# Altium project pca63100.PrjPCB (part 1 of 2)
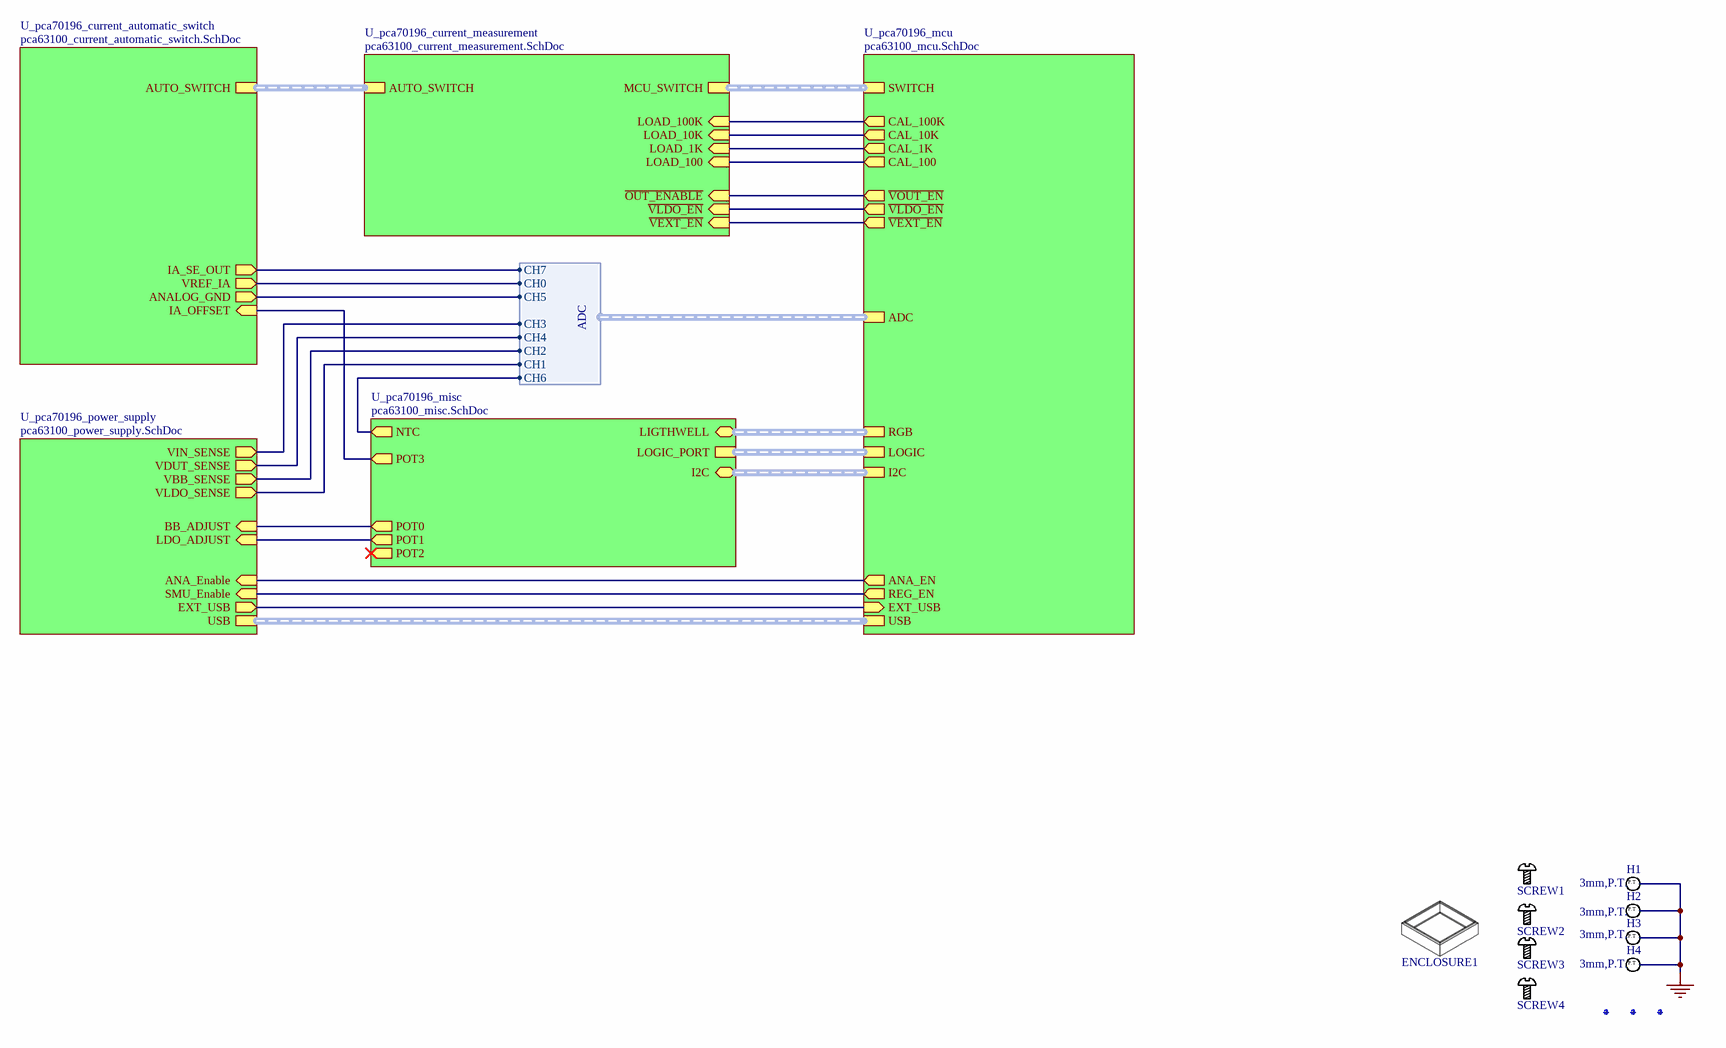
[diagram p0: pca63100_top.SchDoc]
Author: HANY; BoardThickness: 1.6mm; BoardTitle: Power Profiler Kit II; NrOfLayers: 4; Organization: Nordic Semiconductor; PCAName: pca63100; PCBNumber: 400491; PCBRevision: 0016HANY; PCBStackup: 4001; ProjectName: Power Profiler Kit II; ProjectNumber: PCA63100; Revision: 1.0.1; SilkscreenColor: White; SoldermaskColor: Blue; SurfaceFinish: ENIG
6 sheets, 280 parts. Net scope: hierarchical (ports join the sheet entries above them; power ports are global).
Board files: 400491.PcbDoc, 400491_panel.PcbDoc
Sheets:
  pca63100_top.SchDoc
    U_pca70196_current_automatic_switch = pca63100_current_automatic_switch.SchDoc
    U_pca70196_current_measurement = pca63100_current_measurement.SchDoc
    U_pca70196_power_supply = pca63100_power_supply.SchDoc
    U_pca70196_misc = pca63100_misc.SchDoc
    U_pca70196_mcu = pca63100_mcu.SchDoc

## Sheet pca63100_top.SchDoc: Power Profiler Kit II
size A3; Organization: Nordic Semiconductor; Revision: 1.0.1; SheetNumber: 1; SheetTotal: 6; Author: HANY; CompanyName: Nordic Semiconductor; DrawnBy: HANY; DocumentSize: A3

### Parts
ENCLOSURE1  Plastic Enclosure  [Enclosure_PPK2]  (value not drawn)
Fid1  Fiducial mark  [Fiducial_Round-Square]  (value not drawn)  (no BOM)
Fid2  Fiducial mark  [Fiducial_Round-Square]  (value not drawn)  (no BOM)
Fid3  Fiducial mark  [Fiducial_Round-Square]  (value not drawn)  (no BOM)
H1  3mm,P.T.  [HOLE_PT_3MM]  (no BOM)
H2  3mm,P.T.  [HOLE_PT_3MM]  (no BOM)
H3  3mm,P.T.  [HOLE_PT_3MM]  (no BOM)
H4  3mm,P.T.  [HOLE_PT_3MM]  (no BOM)
SCREW1  Screw  [Screw_25x50_pan_tx]  (value not drawn)
SCREW2  Screw  [Screw_25x50_pan_tx]  (value not drawn)
SCREW3  Screw  [Screw_25x50_pan_tx]  (value not drawn)
SCREW4  Screw  [Screw_25x50_pan_tx]  (value not drawn)

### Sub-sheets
U_pca70196_current_automatic_switch = pca63100_current_automatic_switch.SchDoc: IA_SE_OUT (out), IA_OFFSET (in), AUTO_SWITCH (harness SW), VREF_IA (out), ANALOG_GND (out)
U_pca70196_current_measurement = pca63100_current_measurement.SchDoc: ~{OUT_ENABLE} (in), LOAD_100 (in), LOAD_1K (in), LOAD_100K (in), LOAD_10K (in), ~{VEXT_EN} (in), MCU_SWITCH (harness SW), AUTO_SWITCH (harness SW), ~{VLDO_EN} (in)
U_pca70196_mcu = pca63100_mcu.SchDoc: RGB (harness LED), SWITCH (harness SW), I2C (harness I2C), ADC (harness ADC), CAL_10K (out), USB (harness USB), CAL_100K (out), CAL_1K (out), ~{VEXT_EN} (out), CAL_100 (out), ~{VLDO_EN} (out), ~{VOUT_EN} (out), EXT_USB (in), REG_EN (out), ANA_EN (out), LOGIC (harness LP)
U_pca70196_misc = pca63100_misc.SchDoc: POT0 (out), POT1 (out), POT2 (out), POT3 (out), LIGTHWELL (bidir, harness LED), I2C (bidir, harness I2C), NTC (out), LOGIC_PORT (harness LP)
U_pca70196_power_supply = pca63100_power_supply.SchDoc: USB (harness USB), BB_ADJUST (in), LDO_ADJUST (in), VDUT_SENSE (out), VIN_SENSE (out), VLDO_SENSE (out), VBB_SENSE (out), EXT_USB (out), ANA_Enable (in), SMU_Enable (in)

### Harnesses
ADC: CH0, CH1, CH2, CH3, CH4, CH5, CH6, CH7

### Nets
GND: H1.1 H2.1 H3.1 H4.1
P0.02/AIN0_VREF_IA: sheet U_pca70196_current_automatic_switch/VREF_IA, sheet U_pca70196_mcu/ADC.CH0
P0.03/AIN1_VLDO: sheet U_pca70196_power_supply/VLDO_SENSE, sheet U_pca70196_mcu/ADC.CH1
P0.04/AIN2_VBB: sheet U_pca70196_power_supply/VBB_SENSE, sheet U_pca70196_mcu/ADC.CH2
P0.05/AIN3_VIN: sheet U_pca70196_power_supply/VIN_SENSE, sheet U_pca70196_mcu/ADC.CH3
P0.06_VEXT_EN: sheet U_pca70196_current_measurement/~{VEXT_EN}, sheet U_pca70196_mcu/~{VEXT_EN}
P0.07_VLDO_EN: sheet U_pca70196_current_measurement/~{VLDO_EN}, sheet U_pca70196_mcu/~{VLDO_EN}
P0.08_ANA_EN: sheet U_pca70196_power_supply/ANA_Enable, sheet U_pca70196_mcu/ANA_EN
P0.20_CAL100K: sheet U_pca70196_current_measurement/LOAD_100K, sheet U_pca70196_mcu/CAL_100K
P0.21_CAL10K: sheet U_pca70196_current_measurement/LOAD_10K, sheet U_pca70196_mcu/CAL_10K
P0.22_CAL1K: sheet U_pca70196_current_measurement/LOAD_1K, sheet U_pca70196_mcu/CAL_1K
P0.23_CAL100: sheet U_pca70196_current_measurement/LOAD_100, sheet U_pca70196_mcu/CAL_100
P0.28/AIN4_VDUT: sheet U_pca70196_power_supply/VDUT_SENSE, sheet U_pca70196_mcu/ADC.CH4
P0.29/AIN5_AGND: sheet U_pca70196_current_automatic_switch/ANALOG_GND, sheet U_pca70196_mcu/ADC.CH5
P0.30/AIN6_NTC: sheet U_pca70196_misc/NTC, sheet U_pca70196_mcu/ADC.CH6
P0.31/AIN7_VSE_IA: sheet U_pca70196_current_automatic_switch/IA_SE_OUT, sheet U_pca70196_mcu/ADC.CH7
P1.04_VOUT_EN: sheet U_pca70196_current_measurement/~{OUT_ENABLE}, sheet U_pca70196_mcu/~{VOUT_EN}
P1.09_EXT_USB: sheet U_pca70196_power_supply/EXT_USB, sheet U_pca70196_mcu/EXT_USB
P1.13: sheet U_pca70196_power_supply/SMU_Enable, sheet U_pca70196_mcu/REG_EN
POT0: sheet U_pca70196_power_supply/BB_ADJUST, sheet U_pca70196_misc/POT0
POT1: sheet U_pca70196_power_supply/LDO_ADJUST, sheet U_pca70196_misc/POT1
POT3: sheet U_pca70196_current_automatic_switch/IA_OFFSET, sheet U_pca70196_misc/POT3

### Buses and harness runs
harness sheet U_pca70196_current_automatic_switch/AUTO_SWITCH = sheet U_pca70196_current_measurement/AUTO_SWITCH
harness sheet U_pca70196_current_measurement/MCU_SWITCH = sheet U_pca70196_mcu/SWITCH
harness sheet U_pca70196_mcu/I2C = sheet U_pca70196_misc/I2C
harness sheet U_pca70196_mcu/LOGIC = sheet U_pca70196_misc/LOGIC_PORT
harness sheet U_pca70196_mcu/RGB = sheet U_pca70196_misc/LIGTHWELL
harness sheet U_pca70196_mcu/USB = sheet U_pca70196_power_supply/USB

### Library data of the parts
ENCLOSURE1 = Enclosure_PPK2: PPK2 Moulded plastic casing; Manufacturer: Proto Labs, Inc.; Manufacturer Part Number: PPK plexi rev 1.2; Part number IPS: 4971; Pad Count: 0
Fid1-Fid3 = Fid-Mark-Round-Square: Artikkelnr Noca: N.A.; Pad Count: 1
H1-H4 = Hole_3MM_PT: Regular Plate Through, 3mm hole; Manufacturer: Nordic Semiconductor; Artikkelnr Noca: N.A.; Pad Count: 1
SCREW1-SCREW4 = Screw_25x50_pan_tx: Pan head, torx, 2.5x5mm screw; Manufacturer: Bossard; Manufacturer Part Number: 3205129; Part number IPS: 4972; Pad Count: 0

## Sheet pca63100_current_automatic_switch.SchDoc: Power Profiler Kit II
size A3; Organization: Nordic Semiconductor; Revision: 1.0.1; SheetNumber: 5; SheetTotal: 6; Author: HANY; CompanyName: Nordic Semiconductor; DrawnBy: HANY; DocumentSize: A3
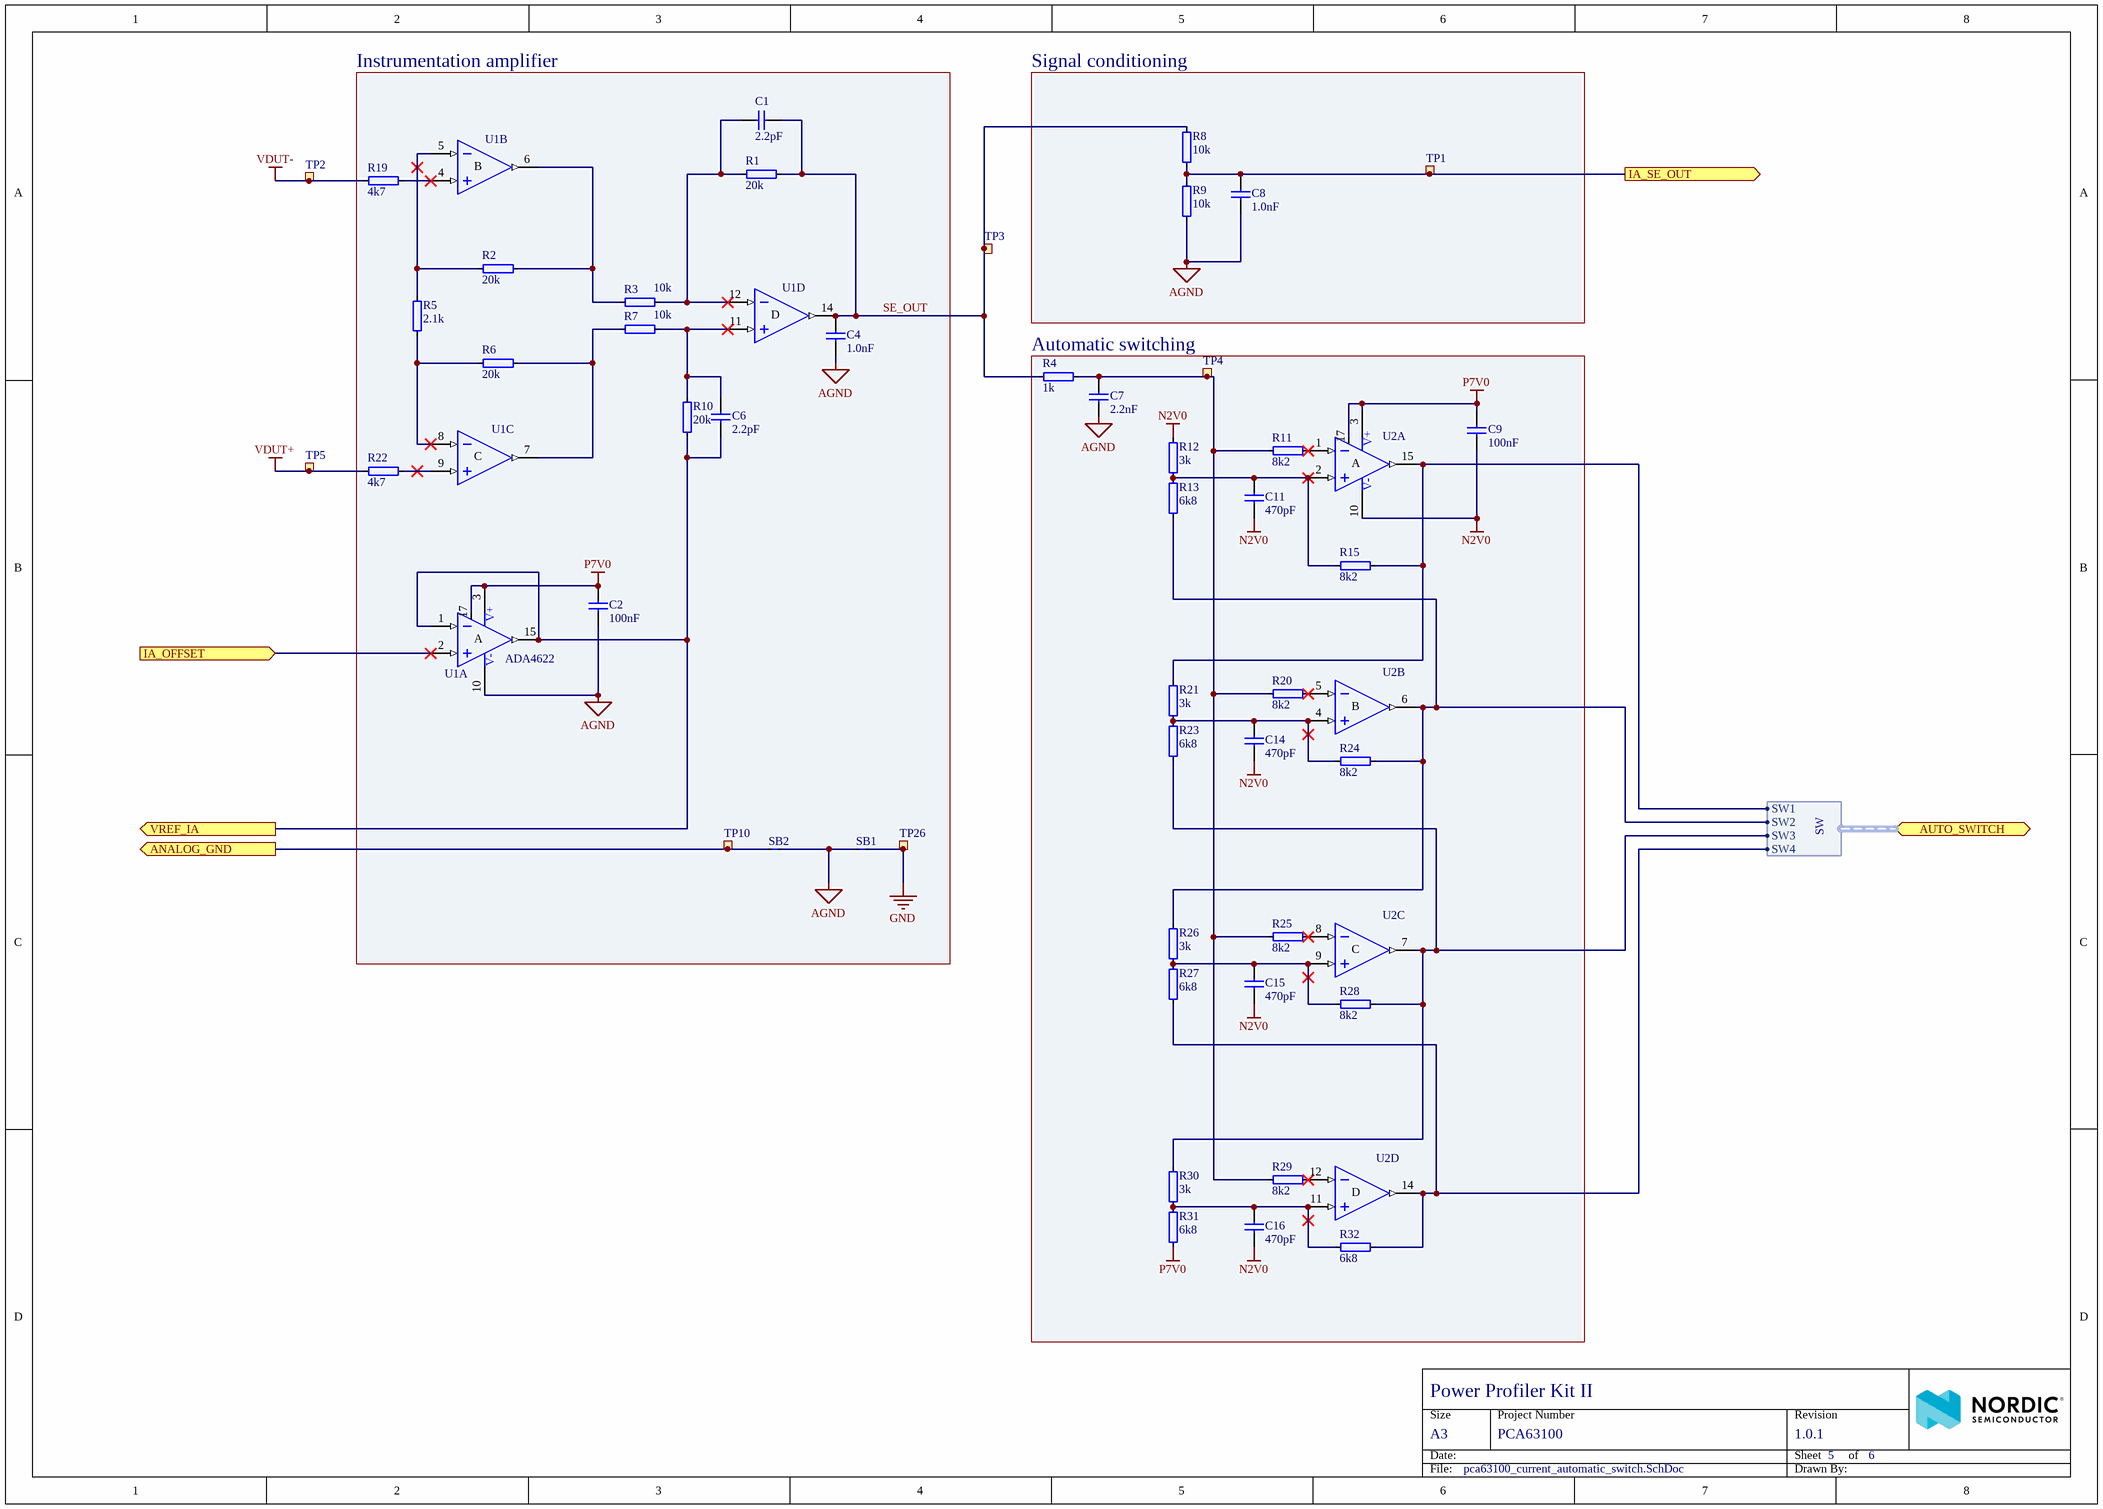
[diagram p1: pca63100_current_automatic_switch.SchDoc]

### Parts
C1  2.2pF  [CAPC0603X03L_C]
C2  100nF  [CAPC0603X03L_C]
C4  1.0nF  [CAPC0603X03L_C]
C6  2.2pF  [CAPC0603X03L_C]
C7  2.2nF  [CAPC0603X03L_C]
C8  1.0nF  [CAPC0603X03L_C]
C9  100nF  [CAPC0603X03L_C]
C11  470pF  [CAPC0603X03L_C]
C14  470pF  [CAPC0603X03L_C]
C15  470pF  [CAPC0603X03L_C]
C16  470pF  [CAPC0603X03L_C]
R1  20k  [RESC0603X03L_C]
R2  20k  [RESC0603X03L_C]
R3  10k  [RESC0603X03L_C]
R4  1k  [RESC0603X03L_C]
R5  2.1k  [RESC0603X03L_C]
R6  20k  [RESC0603X03L_C]
R7  10k  [RESC0603X03L_C]
R8  10k  [RESC0603X03L_C]
R9  10k  [RESC0603X03L_C]
R10  20k  [RESC0603X03L_C]
R11  8k2  [RESC0603X03L_C]
R12  3k  [RESC0603X03L_C]
R13  6k8  [RESC0603X03L_C]
R15  8k2  [RESC0603X03L_C]
R19  4k7  [RESC0603X03L_C]
R20  8k2  [RESC0603X03L_C]
R21  3k  [RESC0603X03L_C]
R22  4k7  [RESC0603X03L_C]
R23  6k8  [RESC0603X03L_C]
R24  8k2  [RESC0603X03L_C]
R25  8k2  [RESC0603X03L_C]
R26  3k  [RESC0603X03L_C]
R27  6k8  [RESC0603X03L_C]
R28  8k2  [RESC0603X03L_C]
R29  8k2  [RESC0603X03L_C]
R30  3k  [RESC0603X03L_C]
R31  6k8  [RESC0603X03L_C]
R32  6k8  [RESC0603X03L_C]
SB1  NetTie_200um  [NetTie_200um]  (value not drawn)  (net tie, no BOM)
SB2  NetTie_200um  [NetTie_200um]  (value not drawn)  (net tie, no BOM)
TP1  Ø0.7mm,SMD  [TP_SMD_Ø0.7mm]  (value not drawn)  (no BOM)
TP2  Ø0.7mm,SMD  [TP_SMD_Ø0.7mm]  (value not drawn)  (no BOM)
TP3  Ø0.7mm,SMD  [TP_SMD_Ø0.7mm]  (value not drawn)  (no BOM)
TP4  Ø0.7mm,SMD  [TP_SMD_Ø0.7mm]  (value not drawn)  (no BOM)
TP5  Ø0.7mm,SMD  [TP_SMD_Ø0.7mm]  (value not drawn)  (no BOM)
TP10  Ø0.7mm,SMD  [TP_SMD_Ø0.7mm]  (value not drawn)  (no BOM)
TP26  Ø0.7mm,SMD  [TP_SMD_Ø0.7mm]  (value not drawn)  (no BOM)
U1  ADA4622  [QFN65P400X400X80_HS-17N]  (parts A,B,C,D of 4)
U2  ADA4622  [QFN65P400X400X80_HS-17N]  (value not drawn)  (parts A,B,C,D of 4)

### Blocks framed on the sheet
Instrumentation amplifier: C1 C2 C4 C6 R1-R3 R5-R7 R10 R19 R22 SB1 SB2 TP10 TP26 U1
Signal conditioning: C8 R8 R9 TP1
Automatic switching: C7 C9 C11 C14-C16 R4 R11-R13 R15 R20 R21 R23-R32 TP4 U2

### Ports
ANALOG_GND (out), AUTO_SWITCH (bidir, harness SW), IA_OFFSET (in), IA_SE_OUT (out), VREF_IA (out)

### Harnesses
SW: SW1, SW2, SW3, SW4

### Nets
AGND: C2.2 C4.1 C7.1 C8.1 R9.1 SB1.1 SB2.2 U1.10(VSS)
GND: SB1.2 TP26.1
N2V0: C9.1 C11.1 C14.1 C15.1 C16.1 R12.2 U2.10(VSS)
P7V0: C2.1 C9.2 R31.1 U1.3(VDD) U1.17(EPAD) U2.3(VDD) U2.17(EPAD)
VDUT+: R22.2 TP5.1
VDUT-: R19.2 TP2.1
AUTO_SW1: R15.2 R21.2 U2.15(OUTA) ; port AUTO_SWITCH.SW1
AUTO_SW2: R13.1 R24.2 R26.2 U2.6(OUTB) ; port AUTO_SWITCH.SW2
AUTO_SW3: R23.1 R28.2 R30.2 U2.7(OUTC) ; port AUTO_SWITCH.SW3
AUTO_SW4: R27.1 R32.2 U2.14(OUTD) ; port AUTO_SWITCH.SW4
P0.02/AIN0_VREF_IA: C6.1 R10.1 U1.1(IN_A-) U1.15(OUTA) ; port VREF_IA
P0.29/AIN5_AGND: SB2.1 TP10.1 ; port ANALOG_GND
P0.31/AIN7_VSE_IA: C8.2 R8.2 R9.2 TP1.1 ; port IA_SE_OUT
POT3: U1.2(IN_A+) ; port IA_OFFSET
SE_OUT: C1.2 C4.2 R1.2 R4.1 R8.1 TP3.1 U1.14(OUTD)
NetC1_1: C1.1 R1.1 R3.2 U1.12(IN_D-)
NetC6_2: C6.2 R7.2 R10.2 U1.11(IN_D+)
NetC7_2: C7.2 R4.2 R11.1 R20.1 R25.1 R29.1 TP4.1
NetC11_2: C11.2 R12.1 R13.2 R15.1 U2.2(IN_A+)
NetC14_2: C14.2 R21.1 R23.2 R24.1 U2.4(IN_B+)
NetC15_2: C15.2 R26.1 R27.2 R28.1 U2.9(IN_C+)
NetC16_2: C16.2 R30.1 R31.2 R32.1 U2.11(IN_D+)
NetR2_1: R2.1 R5.2 U1.5(IN_B-)
NetR2_2: R2.2 R3.1 U1.6(OUTB)
NetR5_1: R5.1 R6.1 U1.8(IN_C-)
NetR6_2: R6.2 R7.1 U1.7(OUTC)
NetR11_2: R11.2 U2.1(IN_A-)
NetR19_1: R19.1 U1.4(IN_B+)
NetR20_2: R20.2 U2.5(IN_B-)
NetR22_1: R22.1 U1.9(IN_C+)
NetR25_2: R25.2 U2.8(IN_C-)
NetR29_2: R29.2 U2.12(IN_D-)

Not connected (* = marked no-connect by the designer): U1 13(NIC) 16(NIC); U2 13(NIC) 16(NIC)

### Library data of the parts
C1 C6 = C0201-2.2p: Chip Cap 0201; Note: Chip Cap 1%; Artikkelnr Noca: N.A.; Pad Count: 2
C2 C9 = C0201-100n: Capacitor, X5R, ±10%; Part number IPS: 00000001248, 00000002505; Note: 16V; Artikkelnr Noca: N.A.; Pad Count: 2
C4 C8 = C0201-1n0: Capacitor, X7R, ±10%; Part number IPS: 00000003206; Note: 16V; Artikkelnr Noca: N.A.; Pad Count: 2
C7 = C0201-2n2: Capacitor, X7R, ±10%, 10V; Part number IPS: 00000001778; Artikkelnr Noca: N.A.; Pad Count: 2
C11 C14-C16 = C0201-470p: Chip Cap 0201; Part number IPS: 00000005775; Note: Chip Cap 1%; Artikkelnr Noca: N.A.; Pad Count: 2
R1 R2 R6 R10 = R0201-20k_0.1%: Resistor, ±0.1%, 0.031W; Part number IPS: 00000004785; Note: Chip Res 0.1%; Artikkelnr Noca: N.A.; Pad Count: 2
R3 R7-R9 = R0201-10k_0.1%: Resistor, ±0.1%, 0.031W; Part number IPS: 00000004786; Note: Chip Res 0.1%; Artikkelnr Noca: N.A.; Pad Count: 2
R4 = R0201-1k0: Resistor, ±1%, 0.05W; Part number IPS: 00000005786; Note: Chip Res 1%; Artikkelnr Noca: N.A.; Pad Count: 2
R5 = R0201-2k1: RES SMD 2.1K OHM 1% 1/20W 0201; Manufacturer: Panasonic; Manufacturer Part Number: ERJ-1GEF2101C; Part number IPS: 00000004787; Note: Chip Res 1%; Artikkelnr Noca: N.A.; Pad Count: 2
R11 R15 R20 R24 R25 R28 R29 = R0201-8k2: Resistor, ±1%, 0.05W; Part number IPS: 00000004788; Note: Chip Res 1%; Artikkelnr Noca: N.A.; Pad Count: 2
R12 R21 R26 R30 = R0201-3k0: Resistor, ±1%, 0.05W; Part number IPS: 00000001688; Note: Chip Res 1%; Artikkelnr Noca: N.A.; Pad Count: 2
R13 R23 R27 R31 R32 = R0201-6k8: Resistor, ±1%, 0.05W; Part number IPS: 00000001705; Note: Chip Res 1%; Artikkelnr Noca: N.A.; Pad Count: 2
R19 R22 = R0201-4k7: Resistor, ±1%, 0.05W; Part number IPS: 00000001706; Note: Chip Res 1%; Artikkelnr Noca: N.A.; Pad Count: 2
SB1 SB2 = NetTie 0.2mm: Net Tie; Artikkelnr Noca: N.A.; Pad Count: 2
TP1-TP5 TP10 TP26 = TP_SMD_Ø0.7MM: 0.7mm circular SMD testpad; Manufacturer: Nordic Semiconductor; Artikkelnr Noca: N.A.; Pad Count: 1
U1 U2 = ADA4622-4: J-FET Amplifier 4 Circuit Rail-to-Rail 16-LFCSP (4x4); Manufacturer: Analog Devices; Manufacturer Part Number: ADA4622-4ACPZ-RL; Part number IPS: 00000004963; Artikkelnr Noca: N.A.; Pad Count: 17

## Sheet pca63100_current_measurement.SchDoc: Power Profiler Kit II
size A3; Organization: Nordic Semiconductor; Revision: 1.0.1; SheetNumber: 4; SheetTotal: 6; Author: HANY; CompanyName: Nordic Semiconductor; DrawnBy: HANY; DocumentSize: A3
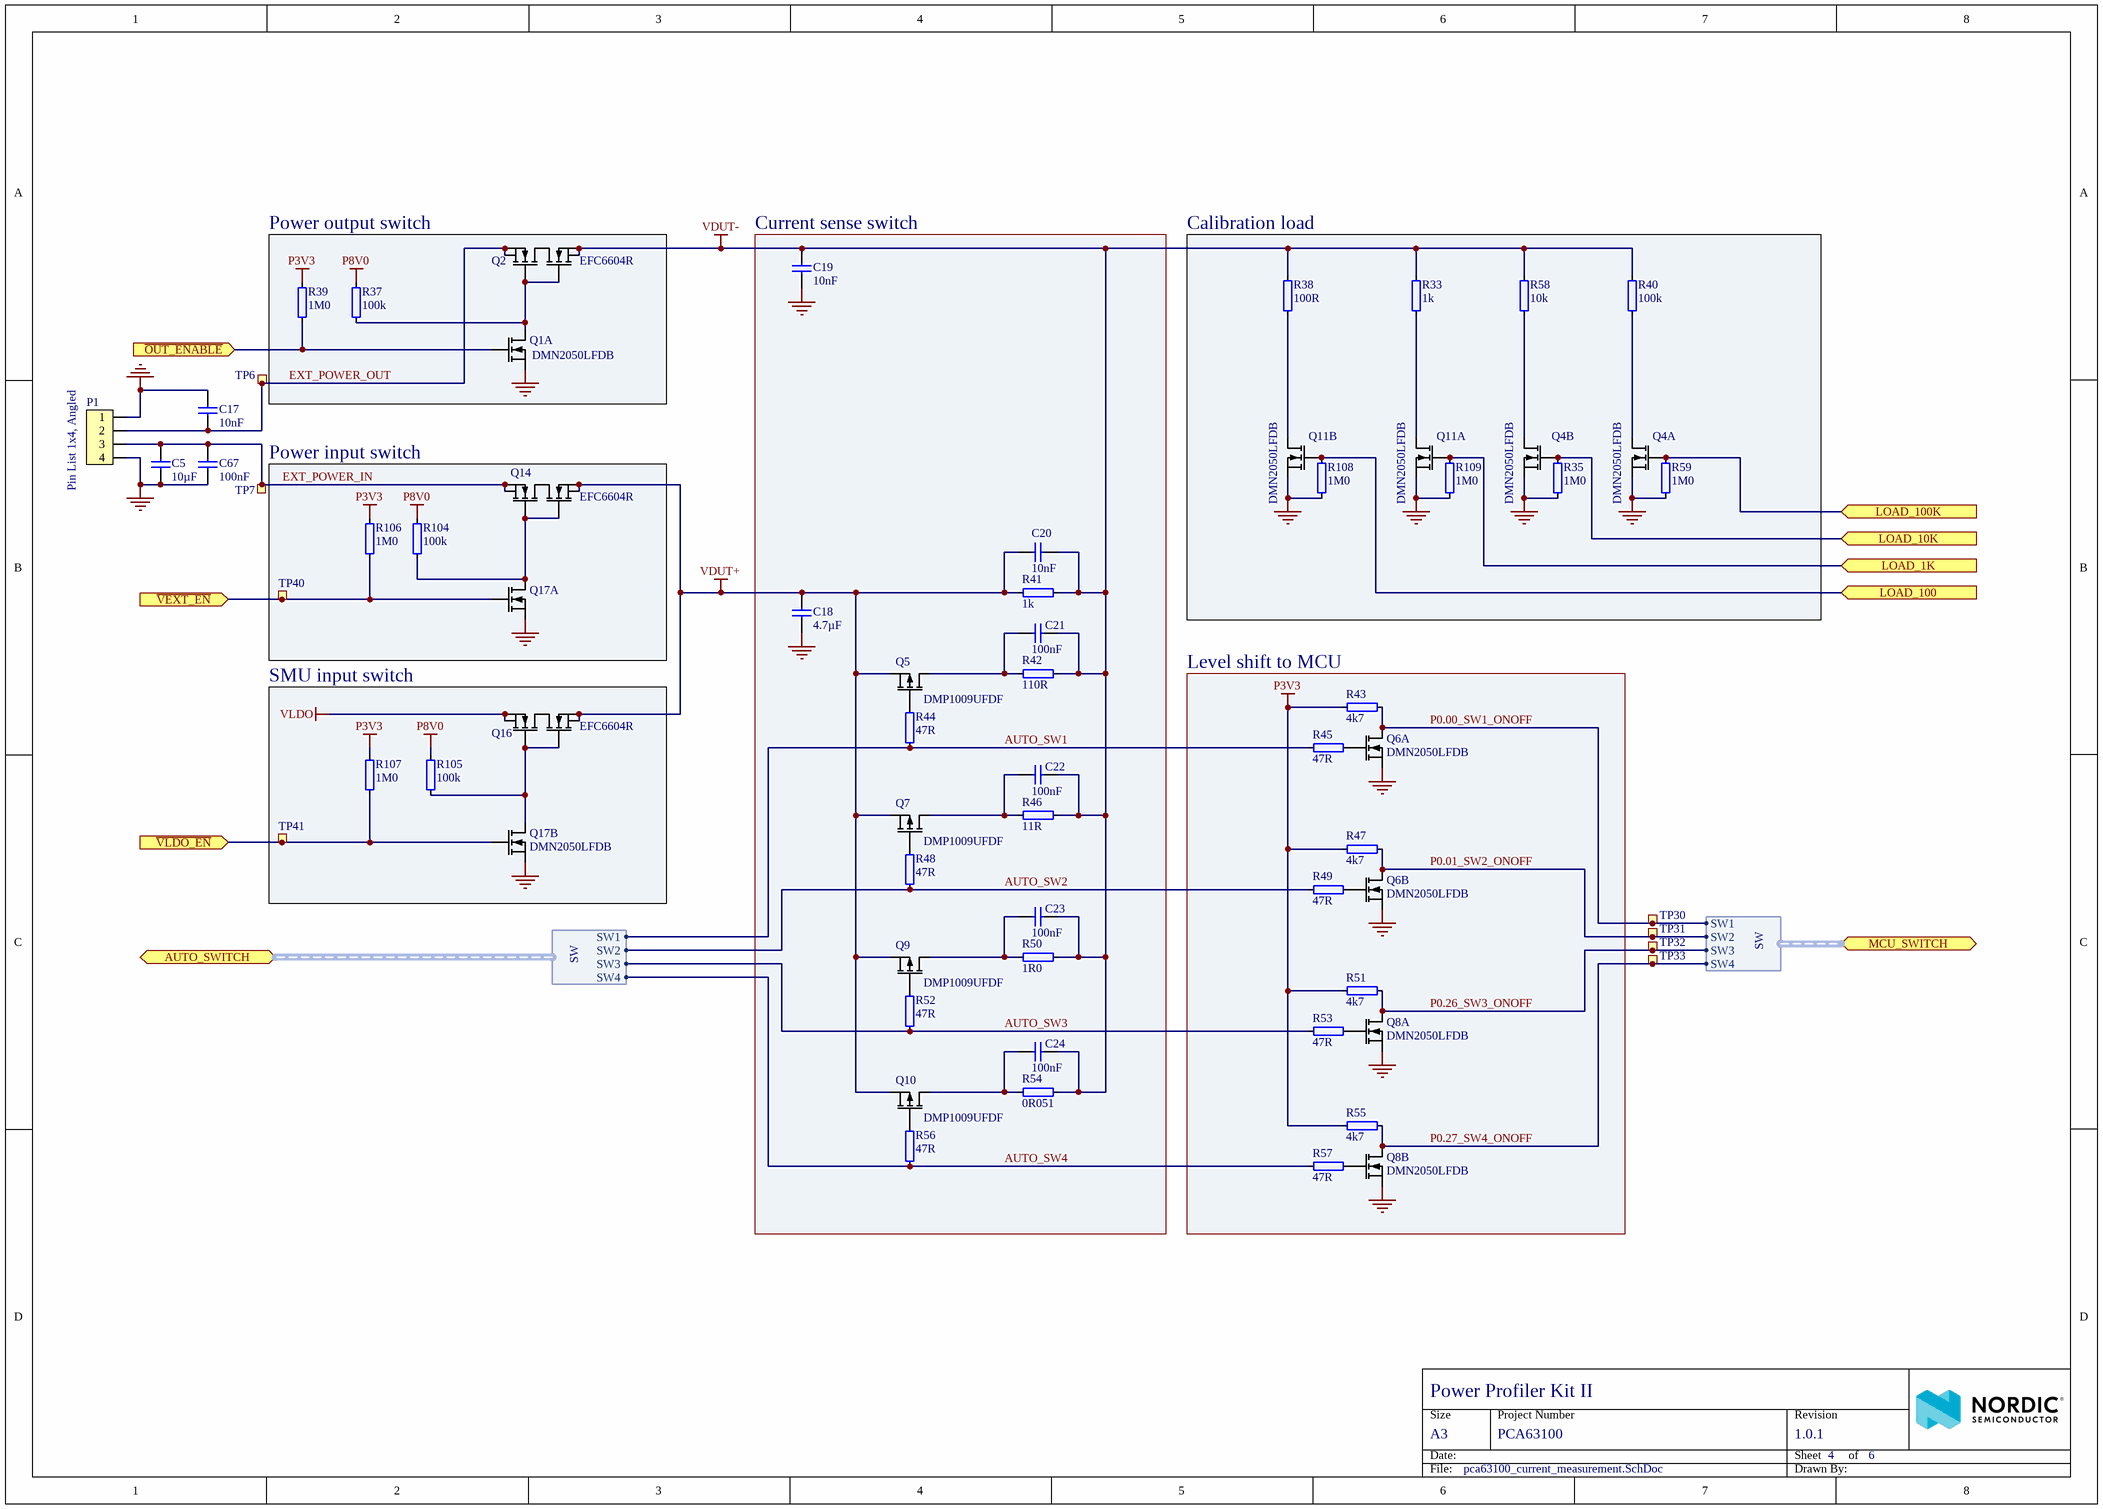
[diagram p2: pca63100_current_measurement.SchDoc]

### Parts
C5  10µF  [CAPC1608X06L]
C17  10nF  [CAPC0603X03L_C]
C18  4.7µF  [CAPC1005X04L]
C19  10nF  [CAPC0603X03L_C]
C20  10nF  [CAPC0603X03L_C]
C21  100nF  [CAPC0603X03L_C]
C22  100nF  [CAPC0603X03L_C]
C23  100nF  [CAPC0603X03L_C]
C24  100nF  [CAPC0603X03L_C]
C67  100nF  [CAPC0603X03L_C]
P1  Pin List 1x4, Angled  [LIST_ANG_1x4-SMD-2.54MM]
Q1  DMN2050LFDB  [DFN65P200X60_HS-6N]  (part A of 2)
Q2  EFC6604R  [BGA6C65P2X3_146X191X22]
Q4  DMN2050LFDB  [DFN65P200X60_HS-6N]  (parts A,B of 2)
Q5  DMP1009UFDF  [UDFN65P200X200X60_HS-6N]
Q6  DMN2050LFDB  [DFN65P200X60_HS-6N]  (parts A,B of 2)
Q7  DMP1009UFDF  [UDFN65P200X200X60_HS-6N]
Q8  DMN2050LFDB  [DFN65P200X60_HS-6N]  (parts A,B of 2)
Q9  DMP1009UFDF  [UDFN65P200X200X60_HS-6N]
Q10  DMP1009UFDF  [UDFN65P200X200X60_HS-6N]
Q11  DMN2050LFDB  [DFN65P200X60_HS-6N]  (parts A,B of 2)
Q14  EFC6604R  [BGA6C65P2X3_146X191X22]
Q16  EFC6604R  [BGA6C65P2X3_146X191X22]
Q17  DMN2050LFDB  [DFN65P200X60_HS-6N]  (value not drawn)  (parts A,B of 2)
R33  1k  [RESC1005X04L]
R35  1M0  [RESC0603X03L_C]
R37  100k  [RESC0603X03L_C]
R38  100R  [RESC2012X11L]
R39  1M0  [RESC0603X03L_C]
R40  100k  [RESC1005X04L]
R41  1k  [RESC1005X04L]
R42  110R  [RESC1005X04L]
R43  4k7  [RESC0603X03L_C]
R44  47R  [RESC0603X03L_C]
R45  47R  [RESC0603X03L_C]
R46  11R  [RESC1005X04L]
R47  4k7  [RESC0603X03L_C]
R48  47R  [RESC0603X03L_C]
R49  47R  [RESC0603X03L_C]
R50  1R0  [RESC1005X04L]
R51  4k7  [RESC0603X03L_C]
R52  47R  [RESC0603X03L_C]
R53  47R  [RESC0603X03L_C]
R54  0R051  [RESC1005X04L]
R55  4k7  [RESC0603X03L_C]
R56  47R  [RESC0603X03L_C]
R57  47R  [RESC0603X03L_C]
R58  10k  [RESC0603X03L_C]
R59  1M0  [RESC0603X03L_C]
R104  100k  [RESC0603X03L_C]
R105  100k  [RESC0603X03L_C]
R106  1M0  [RESC0603X03L_C]
R107  1M0  [RESC0603X03L_C]
R108  1M0  [RESC0603X03L_C]
R109  1M0  [RESC0603X03L_C]
TP6  Ø1.5mm,SMD  [TP_SMD_Ø1.5mm]  (value not drawn)  (no BOM)
TP7  Ø1.5mm,SMD  [TP_SMD_Ø1.5mm]  (value not drawn)  (no BOM)
TP30  Ø0.7mm,SMD  [TP_SMD_Ø0.7mm]  (value not drawn)  (no BOM)
TP31  Ø0.7mm,SMD  [TP_SMD_Ø0.7mm]  (value not drawn)  (no BOM)
TP32  Ø0.7mm,SMD  [TP_SMD_Ø0.7mm]  (value not drawn)  (no BOM)
TP33  Ø0.7mm,SMD  [TP_SMD_Ø0.7mm]  (value not drawn)  (no BOM)
TP40  Ø0.7mm,SMD  [TP_SMD_Ø0.7mm]  (value not drawn)  (no BOM)
TP41  Ø0.7mm,SMD  [TP_SMD_Ø0.7mm]  (value not drawn)  (no BOM)

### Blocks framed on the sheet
Power output switch: Q1 Q2 R37 R39
Current sense switch: C18-C24 Q5 Q7 Q9 Q10 R41 R42 R44 R46 R48 R50 R52 R54 R56
Calibration load: Q4 Q11 R33 R35 R38 R40 R58 R59 R108 R109
Power input switch: Q14 Q17 R104 R106 TP40
SMU input switch: Q16 Q17 R105 R107 TP41
Level shift to MCU: Q6 Q8 R43 R45 R47 R49 R51 R53 R55 R57

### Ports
AUTO_SWITCH (bidir, harness SW), LOAD_1K (in), LOAD_10K (in), LOAD_100 (in), LOAD_100K (in), MCU_SWITCH (bidir, harness SW), ~{OUT_ENABLE} (in), ~{VEXT_EN} (in), ~{VLDO_EN} (in)

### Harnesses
SW: SW1, SW2, SW3, SW4

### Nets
GND: C5.2 C17.1 C18.2 C19.1 C67.2 P1.1 P1.4 Q1.1(S1) Q4.1(S1) Q4.4(S2) Q6.1(S1) Q6.4(S2) Q8.1(S1) Q8.4(S2) Q11.1(S1) Q11.4(S2) Q17.1(S1) Q17.4(S2) R35.1 R59.1 R108.1 R109.1
P3V3: R39.2 R43.2 R47.2 R51.2 R55.2 R106.2 R107.2
P8V0: R37.1 R104.2 R105.2
VDUT+: C18.1 C20.1 Q5.2(S) Q7.2(S) Q9.2(S) Q10.2(S) Q14.1(S1) Q14.3(S2) Q16.1(S1) Q16.3(S2) R41.1
VDUT-: C19.2 C20.2 C21.2 C22.2 C23.2 C24.2 Q2.1(S1) Q2.3(S2) R33.1 R38.2 R40.2 R41.2 R42.2 R46.2 R50.2 R54.1 R58.1
VLDO: Q16.4(S2) Q16.6(S2)
AUTO_SW1: R44.1 R45.2 ; port AUTO_SWITCH.SW1
AUTO_SW2: R48.1 R49.2 ; port AUTO_SWITCH.SW2
AUTO_SW3: R52.1 R53.2 ; port AUTO_SWITCH.SW3
AUTO_SW4: R56.1 R57.2 ; port AUTO_SWITCH.SW4
EXT_POWER_IN: C5.1 C67.1 P1.3 Q14.4(S2) Q14.6(S2) TP7.1
EXT_POWER_OUT: C17.2 P1.2 Q2.4(S2) Q2.6(S2) TP6.1
P0.00_SW1_ONOFF: Q6.6(D1) R43.1 TP30.1 ; port MCU_SWITCH.SW1
P0.01_SW2_ONOFF: Q6.3(D2) R47.1 TP31.1 ; port MCU_SWITCH.SW2
P0.06_VEXT_EN: Q17.2(G1) R106.1 TP40.1 ; port ~{VEXT_EN}
P0.07_VLDO_EN: Q17.5(G2) R107.1 TP41.1 ; port ~{VLDO_EN}
P0.20_CAL100K: Q4.2(G1) R59.2 ; port LOAD_100K
P0.21_CAL10K: Q4.5(G2) R35.2 ; port LOAD_10K
P0.22_CAL1K: Q11.2(G1) R109.2 ; port LOAD_1K
P0.23_CAL100: Q11.5(G2) R108.2 ; port LOAD_100
P0.26_SW3_ONOFF: Q8.6(D1) R51.1 TP32.1 ; port MCU_SWITCH.SW3
P0.27_SW4_ONOFF: Q8.3(D2) R55.1 TP33.1 ; port MCU_SWITCH.SW4
P1.04_VOUT_EN: Q1.2(G1) R39.1 ; port ~{OUT_ENABLE}
NetC21_1: C21.1 Q5.3(D) R42.1
NetC22_1: C22.1 Q7.3(D) R46.1
NetC23_1: C23.1 Q9.3(D) R50.1
NetC24_1: C24.1 Q10.3(D) R54.2
NetQ1_6: Q1.6(D1) Q2.2(G1) Q2.5(G2) R37.2
NetQ4_3: Q4.3(D2) R58.2
NetQ4_6: Q4.6(D1) R40.1
NetQ5_1: Q5.1(G) R44.2
NetQ6_2: Q6.2(G1) R45.1
NetQ6_5: Q6.5(G2) R49.1
NetQ7_1: Q7.1(G) R48.2
NetQ8_2: Q8.2(G1) R53.1
NetQ8_5: Q8.5(G2) R57.1
NetQ9_1: Q9.1(G) R52.2
NetQ10_1: Q10.1(G) R56.2
NetQ11_3: Q11.3(D2) R38.1
NetQ11_6: Q11.6(D1) R33.2
NetQ14_2: Q14.2(G1) Q14.5(G2) Q17.6(D1) R104.1
NetQ16_2: Q16.2(G1) Q16.5(G2) Q17.3(D2) R105.1

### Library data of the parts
C5 = 0603-10u-10V-X7T-GRM188: CAP CER 10UF 10V X7T 0603; Manufacturer: Murata; Manufacturer Part Number: GRM188D71A106MA73; Part number IPS: 00000004696; Note: 10VDC; Artikkelnr Noca: N.A; Pad Count: 2
C17 C19 C20 = C0201-10n: Capacitor, X7R, ±10%; Part number IPS: 00000003480; Note: 10V; Artikkelnr Noca: N.A.; Pad Count: 2
C18 = C0402-4µ7: Capacitor, X5R, ±20%; Part number IPS: 00000001251, 00000007165; Note: 10V; Artikkelnr Noca: 20039482; Pad Count: 2
C21-C24 C67 = C0201-100n: as C2 on sheet pca63100_current_automatic_switch
P1 = Pin List Ang 1x4 SMD, 2.54mm: Pin List 1x4, 2.54mm (100mil), Right Angled, SMD; Part number IPS: 00000004780; Artikkelnr Noca: N.A.; Pad Count: 4
Q1 Q4 Q6 Q8 Q11 Q17 = DMN2050LFDB: Dual N Ch MOFET, 3.3A, 45mOhm @ 5A, 4.5V, 730mW; Manufacturer: Diodes Incorporated; Manufacturer Part Number: DMN2050LFDB-7; Part number IPS: 00000004782; Artikkelnr Noca: N.A.; Pad Count: 6
Q2 Q14 Q16 = EFC6604R: Dual MOSFET, Dual N Channel, 13 A, 12 V, 0.009 ohm, 4.5 V, 2.5 V; Manufacturer: ON Semiconductor; Manufacturer Part Number: EFC6604R-TR; Part number IPS: 00000004783; Artikkelnr Noca: N.A.; Pad Count: 6
Q5 Q7 Q9 Q10 = DMP1009UFDF: P Ch MOFET, 11A, 30mOhm max, 2W; Manufacturer: Diodes Incorporated; Part number IPS: 00000004784; Artikkelnr Noca: N.A.; Pad Count: 6
R33 R41 = R0402-1k0_0.1%: Resistor, ±0.1%, 0.063W; Part number IPS: 00000004790; Note: Chip Res 0.1%; Artikkelnr Noca: 27469397; Pad Count: 2
R35 R39 R59 R106-R109 = R0201-1M0: Resistor, ±1%, 0.05W; Part number IPS: 00000001418; Note: Chip Res 1%; Artikkelnr Noca: N.A.; Pad Count: 2
R37 R104 R105 = R0201-100k: Resistor, ±1%, 0.05W; Part number IPS: 00000001419; Note: Chip Res 1%; Artikkelnr Noca: N.A.; Pad Count: 2
R38 = R0805-100: Resistor, ±1%, 0.125W; Part number IPS: 00000004791; Note: Chip Res 1%; Artikkelnr Noca: 27089049; Pad Count: 2
R40 = R0402-100k_0.1%: Resistor, ±0.1%, 0.063W; Part number IPS: 00000004792; Note: Chip Res 1%; Artikkelnr Noca: N.A.; Pad Count: 2
R42 = R0402-110: Resistor, ±1%, 0.063W; Part number IPS: 00000004793; Note: Chip Res 1%; Artikkelnr Noca: N.A.; Pad Count: 2
R43 R47 R51 R55 = R0201-4k7: as R19 on sheet pca63100_current_automatic_switch
R44 R45 R48 R49 R52 R53 R56 R57 = R0201-47R: Resistor, ±1%, 0.05W; Part number IPS: 00000004794; Note: Chip Res 1%; Artikkelnr Noca: N.A.; Pad Count: 2
R46 = R0402-11R: Resistor, ±1%, 0.063W; Part number IPS: 00000007807; Note: Chip Res 1%; Artikkelnr Noca: N.A.; Pad Count: 2
R50 = R0402-1R0: Resistor, ±1%, 0.063W; Part number IPS: 00000004795; Note: Chip Res 1%; Artikkelnr Noca: 27049001; Pad Count: 2
R54 = R0402-0R051: RES SMD 0.051 OHM 1% 1/4W 0402; Manufacturer: Panasonic; Manufacturer Part Number: ERJ-2BWFR051X; Part number IPS: 00000004796; Note: Chip Res 1%; Artikkelnr Noca: N.A.; Pad Count: 2
R58 = R0201-10k_0.1%: as R3 on sheet pca63100_current_automatic_switch
TP6 TP7 = TP_SMD_Ø1.5MM: 1.5mm circular SMD testpad; Manufacturer: Nordic Semiconductor; Artikkelnr Noca: N.A.; Pad Count: 1
TP30-TP33 TP40 TP41 = TP_SMD_Ø0.7MM: as TP1 on sheet pca63100_current_automatic_switch

## Sheet pca63100_power_supply.SchDoc: Power Profiler Kit II
size A3; Organization: Nordic Semiconductor; Revision: 1.0.1; SheetNumber: 3; SheetTotal: 6; Author: HANY; CompanyName: Nordic Semiconductor; DrawnBy: HANY; DocumentSize: A3
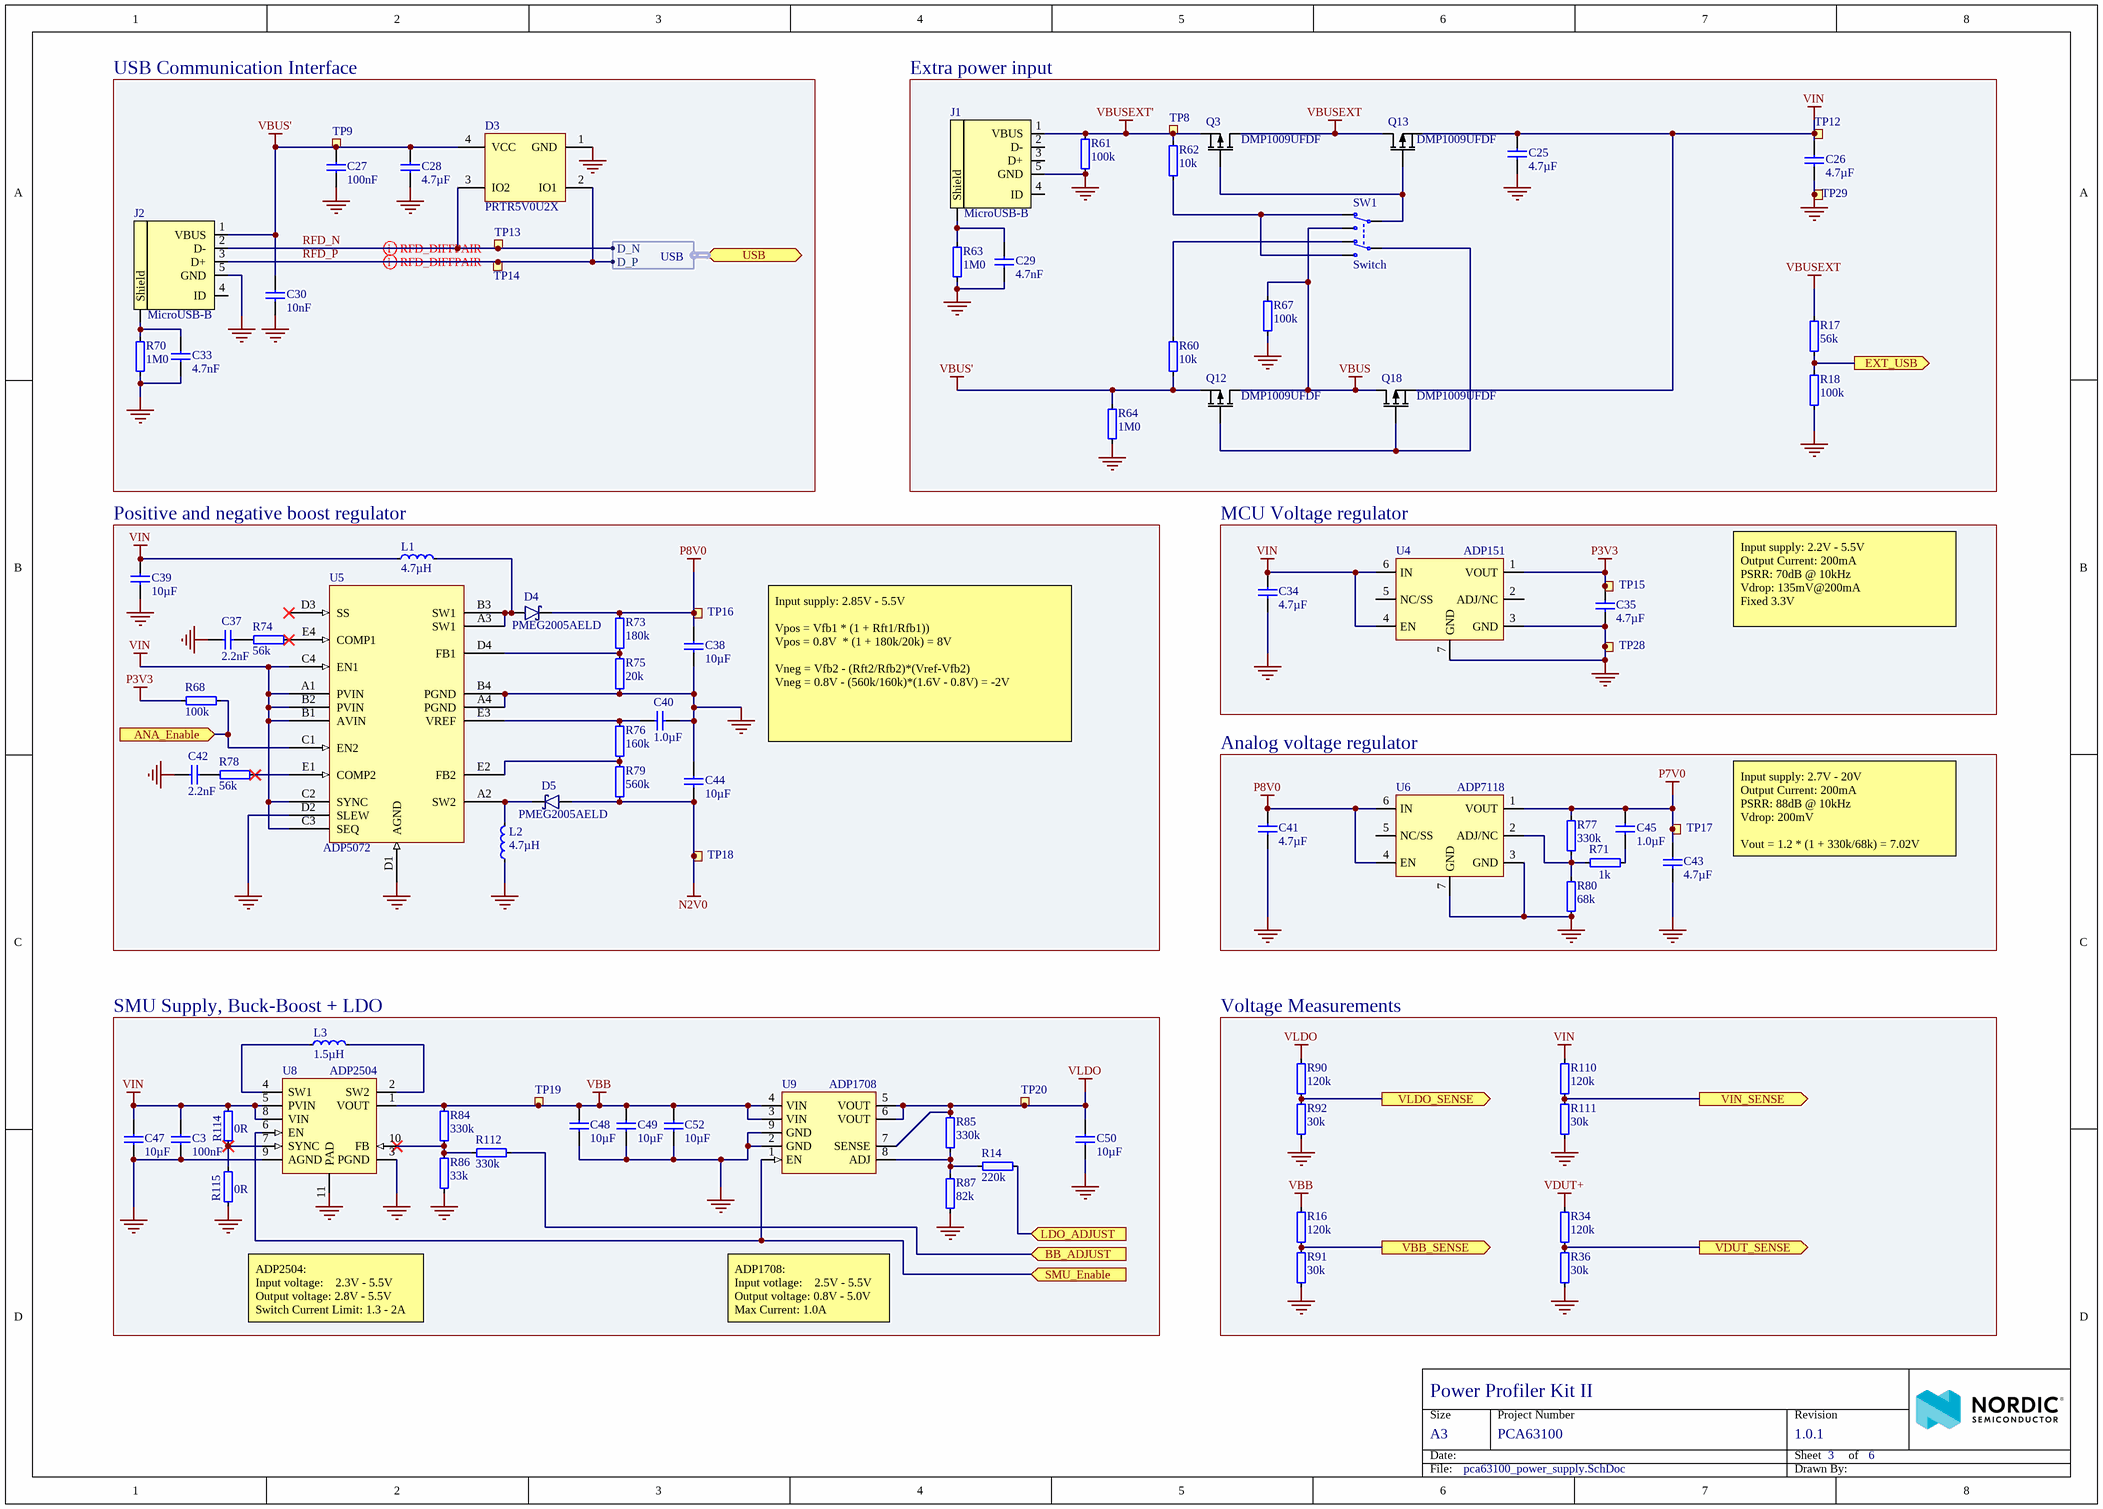
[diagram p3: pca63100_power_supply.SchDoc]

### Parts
C3  100nF  [CAPC0603X03L_C]
C25  4.7µF  [CAPC1005X04L]
C26  4.7µF  [CAPC1005X04L]
C27  100nF  [CAPC0603X03L_C]
C28  4.7µF  [CAPC1005X04L]
C29  4.7nF  [CAPC0603X03L_C]
C30  10nF  [CAPC0603X03L_C]
C33  4.7nF  [CAPC0603X03L_C]
C34  4.7µF  [CAPC1005X04L]
C35  4.7µF  [CAPC1005X04L]
C37  2.2nF  [CAPC0603X03L_C]
C38  10µF  [CAPC1608X06L]
C39  10µF  [CAPC1608X06L]
C40  1.0µF  [CAPC1005X04L]
C41  4.7µF  [CAPC1005X04L]
C42  2.2nF  [CAPC0603X03L_C]
C43  4.7µF  [CAPC1005X04L]
C44  10µF  [CAPC1608X06L]
C45  1.0µF  [CAPC0603X03L_C]
C47  10µF  [CAPC1608X06L]
C48  10µF  [CAPC1608X06L]
C49  10µF  [CAPC1608X06L]
C50  10µF  [CAPC1608X06L]
C52  10µF  [CAPC1608X06L]
D3  PRTR5V0U2X  [SOT190P230X110-4L]
D4  PMEG2005AELD  [DFN1006D-2]
D5  PMEG2005AELD  [DFN1006D-2]
J1  MicroUSB-B  [USB-Micro-B-RA-SMD-PiP]
J2  MicroUSB-B  [USB-Micro-B-RA-SMD-PiP]
L1  4.7µH  [IND_EPL2014]
L2  4.7µH  [IND_EPL2014]
L3  1.5µH  [TY-NR3015]
Q3  DMP1009UFDF  [UDFN65P200X200X60_HS-6N]
Q12  DMP1009UFDF  [UDFN65P200X200X60_HS-6N]
Q13  DMP1009UFDF  [UDFN65P200X200X60_HS-6N]
Q18  DMP1009UFDF  [UDFN65P200X200X60_HS-6N]
R14  220k  [RESC0603X03L_C]
R16  120k  [RESC0603X03L_C]
R17  56k  [RESC0603X03L_C]
R18  100k  [RESC0603X03L_C]
R34  120k  [RESC0603X03L_C]
R36  30k  [RESC0603X03L_C]
R60  10k  [RESC0603X03L_C]
R61  100k  [RESC0603X03L_C]
R62  10k  [RESC0603X03L_C]
R63  1M0  [RESC0603X03L_C]
R64  1M0  [RESC0603X03L_C]
R67  100k  [RESC0603X03L_C]
R68  100k  [RESC0603X03L_C]
R70  1M0  [RESC0603X03L_C]
R71  1k  [RESC0603X03L_C]
R73  180k  [RESC0603X03L_C]
R74  56k  [RESC0603X03L_C]
R75  20k  [RESC0603X03L_C]
R76  160k  [RESC1005X04L]
R77  330k  [RESC0603X03L_C]
R78  56k  [RESC0603X03L_C]
R79  560k  [RESC0603X03L_C]
R80  68k  [RESC0603X03L_C]
R84  330k  [RESC0603X03L_C]
R85  330k  [RESC0603X03L_C]
R86  33k  [RESC0603X03L_C]
R87  82k  [RESC0603X03L_C]
R90  120k  [RESC0603X03L_C]
R91  30k  [RESC0603X03L_C]
R92  30k  [RESC0603X03L_C]
R110  120k  [RESC0603X03L_C]
R111  30k  [RESC0603X03L_C]
R112  330k  [RESC0603X03L_C]
R114  0R  [RESC0603X03L_C]
R115  0R  [RESC0603X03L_C]
SW1  Switch  [Switch-Slide-RA-J-Lead-DPDT-8.5x3.5mm]
TP8  Ø1.5mm,SMD  [TP_SMD_Ø1.5mm]  (value not drawn)  (no BOM)
TP9  Ø1.5mm,SMD  [TP_SMD_Ø1.5mm]  (value not drawn)  (no BOM)
TP12  Ø1.5mm,SMD  [TP_SMD_Ø1.5mm]  (value not drawn)  (no BOM)
TP13  Ø1.5mm,SMD  [TP_SMD_Ø1.5mm]  (value not drawn)  (no BOM)
TP14  Ø1.5mm,SMD  [TP_SMD_Ø1.5mm]  (value not drawn)  (no BOM)
TP15  Ø1.5mm,SMD  [TP_SMD_Ø1.5mm]  (value not drawn)  (no BOM)
TP16  Ø1.5mm,SMD  [TP_SMD_Ø1.5mm]  (value not drawn)  (no BOM)
TP17  Ø1.5mm,SMD  [TP_SMD_Ø1.5mm]  (value not drawn)  (no BOM)
TP18  Ø0.7mm,SMD  [TP_SMD_Ø0.7mm]  (value not drawn)  (no BOM)
TP19  Ø0.7mm,SMD  [TP_SMD_Ø0.7mm]  (value not drawn)  (no BOM)
TP20  Ø1.5mm,SMD  [TP_SMD_Ø1.5mm]  (value not drawn)  (no BOM)
TP28  Ø1.5mm,SMD  [TP_SMD_Ø1.5mm]  (value not drawn)  (no BOM)
TP29  Ø1.5mm,SMD  [TP_SMD_Ø1.5mm]  (value not drawn)  (no BOM)
U4  ADP151  [SON65P200X60_HS-7N]
U5  ADP5072  [BGA20C40P4X5_161X218X56]
U6  ADP7118  [SON65P200X60_HS-7N]
U8  ADP2504  [SON50P300X80-HS-11N]
U9  ADP1708  [SON50P300X80_HS-9N]

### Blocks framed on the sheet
USB Communication Interface: C27 C28 C30 C33 D3 J2 R70 TP9 TP13 TP14
Extra power input: C25 C26 C29 J1 Q3 Q12 Q13 Q18 R17 R18 R60-R64 R67 SW1 TP8 TP12 TP29
Positive and negative boost regulator: C37-C40 C42 C44 D4 D5 L1 L2 R68 R73-R76 R78 R79 TP16 TP18 U5
MCU Voltage regulator: C34 C35 TP15 TP28 U4
Analog voltage regulator: C41 C43 C45 R71 R77 R80 TP17 U6
SMU Supply, Buck-Boost + LDO: C3 C47-C50 C52 L3 R14 R84-R87 R112 R114 R115 TP19 TP20 U8 U9
Voltage Measurements: R16 R34 R36 R90-R92 R110 R111

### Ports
ANA_Enable (in), BB_ADJUST (in), EXT_USB (out), LDO_ADJUST (in), SMU_Enable (in), USB (bidir, harness USB), VBB_SENSE (out), VDUT_SENSE (out), VIN_SENSE (out), VLDO_SENSE (out)

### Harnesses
USB: D_N, D_P

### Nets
GND: C3.2 C25.1 C26.1 C27.2 C28.2 C29.2 C30.2 C33.2 C34.2 C35.1 C37.1 C38.1 C39.2 C40.1 C41.2 C42.1 C43.1 C44.1 C47.2 C48.2 C49.2 C50.2 C52.2 D3.1(GND) J1.5(GND) J2.5(GND) L2.1 R18.1 R36.1 R61.2 R63.2 R64.2 R67.2 R70.2 R75.1 R80.1 R86.1 R87.1 R91.1 R92.1 R111.1 R115.1 TP28.1 TP29.1 U4.3(GND) U4.7(GND) U5.A4(PGND) U5.B4(PGND) U5.D1(AGND) U5.D2(SLEW) U6.3(GND) U6.7(GND) U8.3(PGND) U8.9(AGND) U8.11(PAD) U9.2(GND) U9.9(GND)
N2V0: C44.2 D5.2(A) R79.1 TP18.1
P3V3: C35.2 R68.1 TP15.1 U4.1(VOUT)
P7V0: C43.2 C45.2 R77.2 TP17.1 U6.1(VOUT)
P8V0: C38.2 C41.1 D4.1(C) R73.2 TP16.1 U6.4(EN) U6.6(IN)
VBB: C48.1 C49.1 C52.1 R16.2 R84.2 TP19.1 U8.1(VOUT) U9.3(VIN) U9.4(VIN)
VBUS: Q12.3(D) Q18.3(D) R67.1 SW1.1(N.O-1)
VBUS': C27.1 C28.1 C30.1 D3.4(VCC) J2.1(VBUS) Q12.2(S) R60.2 R64.1 TP9.1
VBUSEXT: Q3.3(D) Q13.3(D) R17.1
VBUSEXT': J1.1(VBUS) Q3.2(S) R61.1 R62.1 TP8.1
VDUT+: R34.2
VIN: C3.1 C25.2 C26.2 C34.1 C39.1 C47.1 L1.1 Q13.2(S) Q18.2(S) R110.2 R114.2 TP12.1 U4.4(EN) U4.6(IN) U5.A1(PVIN) U5.B1(AVIN) U5.B2(PVIN) U5.C2(SYNC) U5.C3(SEQ) U5.C4(EN1) U8.5(PVIN) U8.8(VIN)
VLDO: C50.1 R85.2 R90.2 TP20.1 U9.5(VOUT) U9.6(VOUT) U9.7(SENSE)
P0.03/AIN1_VLDO: R90.1 R92.2 ; port VLDO_SENSE
P0.04/AIN2_VBB: R16.1 R91.2 ; port VBB_SENSE
P0.05/AIN3_VIN: R110.1 R111.2 ; port VIN_SENSE
P0.08_ANA_EN: R68.2 U5.C1(EN2) ; port ANA_Enable
P0.28/AIN4_VDUT: R34.1 R36.2 ; port VDUT_SENSE
P1.09_EXT_USB: R17.2 R18.2 ; port EXT_USB
P1.13: U8.6(EN) U9.1(EN) ; port SMU_Enable
POT0: R112.2 ; port BB_ADJUST
POT1: R14.2 ; port LDO_ADJUST
RFD_N: D3.3(IO2) J2.2(D-) TP13.1 ; port USB.D_N
RFD_P: D3.2(IO1) J2.3(D+) TP14.1 ; port USB.D_P
NetC29_1: C29.1 J1.6(Shield) R63.1
NetC33_1: C33.1 J2.6(Shield) R70.1
NetC37_2: C37.2 R74.1
NetC40_2: C40.2 R76.2 U5.E3(VREF)
NetC42_2: C42.2 R78.1
NetC45_1: C45.1 R71.1
NetD4_2: D4.2(A) L1.2 U5.A3(SW1) U5.B3(SW1)
NetD5_1: D5.1(C) L2.2 U5.A2(SW2)
NetL3_1: L3.1 U8.4(SW1)
NetL3_2: L3.2 U8.2(SW2)
NetQ3_1: Q3.1(G) Q13.1(G) SW1.2(COM-1)
NetQ12_1: Q12.1(G) Q18.1(G) SW1.5(COM-2)
NetR14_1: R14.1 R85.1 R87.2 U9.8(ADJ)
NetR60_1: R60.1 SW1.6(N.C-2)
NetR62_2: R62.2 SW1.3(N.C-1) SW1.4(N.O-2)
NetR71_2: R71.2 R77.1 R80.2 U6.2(ADJ/NC)
NetR73_1: R73.1 R75.2 U5.D4(FB1)
NetR74_2: R74.2 U5.E4(COMP1)
NetR76_1: R76.1 R79.2 U5.E2(FB2)
NetR78_2: R78.2 U5.E1(COMP2)
NetR84_1: R84.1 R86.2 R112.1 U8.10(FB)
NetR114_1: R114.1 R115.2 U8.7(SYNC)

Not connected (* = marked no-connect by the designer): J1 2(D-) 3(D+) 4(ID); J2 4(ID); U4 2(ADJ/NC) 5(NC/SS); U5 D3(SS)*; U6 5(NC/SS)

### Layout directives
differential pair; differential pair class USB2: RFD_N, RFD_P

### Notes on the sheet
- Input supply: 2.2V - 5.5V
  Output Current: 200mA
  PSRR: 70dB @ 10kHz
  Vdrop: 135mV@200mA
  Fixed 3.3V
- Input supply: 2.85V - 5.5V
  Vpos = Vfb1 * (1 + Rft1/Rfb1))
  Vpos = 0.8V  * (1 + 180k/20k) = 8V
  Vneg = Vfb2 - (Rft2/Rfb2)*(Vref-Vfb2)
  Vneg = 0.8V - (560k/160k)*(1.6V - 0.8V) = -2V
- Input supply: 2.7V - 20V
  Output Current: 200mA
  PSRR: 88dB @ 10kHz
  Vdrop: 200mV
  Vout = 1.2 * (1 + 330k/68k) = 7.02V
- ADP2504:
  Input voltage:    2.3V - 5.5V
  Output voltage: 2.8V - 5.5V
  Switch Current Limit: 1.3 - 2A
- ADP1708:
  Input votlage:    2.5V - 5.5V
  Output voltage: 0.8V - 5.0V
  Max Current: 1.0A

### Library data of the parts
C3 C27 = C0201-100n: as C2 on sheet pca63100_current_automatic_switch
C25 C26 C28 C34 C35 C41 C43 = C0402-4µ7: as C18 on sheet pca63100_current_measurement
C29 C33 = C0201-4n7: Chip Cap 0201; Part number IPS: 00000001243; Note: Chip Cap 1%; Artikkelnr Noca: N.A.; Pad Count: 2
C30 = C0201-10n: as C17 on sheet pca63100_current_measurement
C37 C42 = C0201-2n2: as C7 on sheet pca63100_current_automatic_switch
C38 C39 C44 C47-C50 C52 = 0603-10u-10V-X7T-GRM188: as C5 on sheet pca63100_current_measurement
C40 = C0402-1µ0: Capacitor, X5R, ±5%, 6.3V; Part number IPS: 00000007786, 00000003457; Artikkelnr Noca: 20039235; Pad Count: 2
C45 = C0201-1µ0: Capacitor, X5R, ±10%; Part number IPS: 00000001723; Note: 10V; Artikkelnr Noca: N.A.; Pad Count: 2
D3 = PRTR5V0U2X: Ultra low capacitance double rail-to-rail ESD protection diode; Manufacturer: NXP; Part number IPS: 00000009951; Artikkelnr Noca: 10069015; Pad Count: 4
D4 D5 = PMEG2005AELD: DIODE SCHOTTKY 20V 0.5A DFN1006D-2/SOD882D; Manufacturer: NXP; Manufacturer Part Number: PMEG2005AELD, 315; Part number IPS: 00000004695; Artikkelnr Noca: N.A.; Pad Count: 2
J1 J2 = USB-Micro-B-RA-SMD-PiP: MicroUSB-B-SMT; Manufacturer: Allen Creations Corp.; Manufacturer Part Number: AJU55-BS2111-L; 2nd source part number: 609-4616-1-ND; Part number IPS: 00000007790; Artikkelnr Noca: 55029020; Artikkelnr Simpro: N.A.; Pad Count: 5
L1 L2 = EPL2014-472MLC: Shielded Power Inductor EPL2014 Low DCR Ind 4.7 uH 20 % 650mA; Manufacturer: Coilcraft; Part number IPS: 00000004697; Artikkelnr Noca: N.A.; Pad Count: 2
L3 = NR3015-1µ5-1.8A-48mOhm: Ferrite Inductor, Shielded, 1,8A, 48mOhm; Manufacturer: Taiyo Yuden; Manufacturer Part Number: NR3015T1R5N; Part number IPS: 00000004698; Artikkelnr Noca: N.A.; Pad Count: 2
Q3 Q12 Q13 Q18 = DMP1009UFDF: as Q5 on sheet pca63100_current_measurement
R14 = R0201-220k: Resistor, ±1%, 0.05W; Part number IPS: 00000004789; Note: Chip Res 1%; Artikkelnr Noca: N.A.; Pad Count: 2
R16 R34 R90 R110 = R0201-120k: Resistor, ±1%, 0.05W; Part number IPS: 00000001425; Note: Chip Res 1%; Artikkelnr Noca: N.A.; Pad Count: 2
R17 R74 R78 = R0201-56k: Resistor, ±1%, 0.05W; Part number IPS: 00000007882; Note: Chip Res 1%; Artikkelnr Noca: N.A.; Pad Count: 2
R18 R61 R67 R68 = R0201-100k: as R37 on sheet pca63100_current_measurement
R36 R91 R92 R111 = R0201-30k: Resistor, ±1%, 0.05W; Part number IPS: 00000004318; Note: Chip Res 1%; Artikkelnr Noca: N.A.; Pad Count: 2
R60 R62 = R0201-10k_0.1%: as R3 on sheet pca63100_current_automatic_switch
R63 R64 R70 = R0201-1M0: as R35 on sheet pca63100_current_measurement
R71 = R0201-1k0: as R4 on sheet pca63100_current_automatic_switch
R73 = R0201-180k: Resistor, ±1%, 0.05W; Part number IPS: 00000004797; Note: Chip Res 1%; Artikkelnr Noca: N.A.; Pad Count: 2
R75 = R0201-20k_0.1%: as R1 on sheet pca63100_current_automatic_switch
R76 = R0402-160k_0.1%: Resistor, ±0.1%, 0.063W; Part number IPS: 00000004798; Note: Chip Res 0.1%; Artikkelnr Noca: N.A.; Pad Count: 2
R77 R84 R85 R112 = R0201-330k: Resistor, ±1%, 0.05W; Part number IPS: 00000001424; Note: Chip Res 1%; Artikkelnr Noca: N.A.; Pad Count: 2
R79 = R0201-560k: Resistor, ±1%, 0.05W; Part number IPS: 00000004799; Note: Chip Res 1%; Artikkelnr Noca: N.A.; Pad Count: 2
R80 = R0201-68k: Resistor, ±1%, 0.05W; Part number IPS: 00000004800; Note: Chip Res 1%; Artikkelnr Noca: N.A.; Pad Count: 2
R86 = R0201-33k: Resistor, ±1%, 0.05W; Part number IPS: 00000001708; Note: Chip Res 1%; Artikkelnr Noca: N.A.; Pad Count: 2
R87 = R0201-82k: Resistor, ±1%, 0.05W; Part number IPS: 00000004801; Note: Chip Res 1%; Artikkelnr Noca: N.A.; Pad Count: 2
R114 R115 = R0201-0R: Resistor, ±5%, 0.05W; Part number IPS: 00000003245; Note: Chip Res 5%; Artikkelnr Noca: N.A.; Pad Count: 2
SW1 = Switch-Slide-RA-J-Lead-DPDT-8.5x3.5mm_Copal: SMD slide Switch (ON-ON); Manufacturer: Copal Electronics Inc; Manufacturer Part Number: CL-SB-22A-11T; Part number IPS: 00000007811; Artikkelnr Noca: N.A.; Pad Count: 6
TP8 TP9 TP12-TP17 TP20 TP28 TP29 = TP_SMD_Ø1.5MM: as TP6 on sheet pca63100_current_measurement
TP18 TP19 = TP_SMD_Ø0.7MM: as TP1 on sheet pca63100_current_automatic_switch
U4 = ADP151: Ultralow Noise, 200 mA,CMOS Linear Regulator; Manufacturer: Analog Devices; Manufacturer Part Number: ADP151ACPZ-3.3-R7; Part number IPS: 00000004803; Artikkelnr Noca: N.A.; Pad Count: 7
U5 = ADP5072: Boost Switching Regulator IC Positive and Negative (Dual Rail) Adjustable 0.8V 2 Output 600mA, 1A 20-UFBGA,; Manufacturer: Analog Devices; Manufacturer Part Number: ADP5072ACBZ-R7; Part number IPS: 00000004804; Artikkelnr Noca: N.A.; Pad Count: 20
U6 = ADP7118: 20 V, 200 mA, Low Noise,CMOS LDO Linear Regulator; Manufacturer: Analog Devices; Manufacturer Part Number: ADP7118ACPZN-R7; Part number IPS: 00000004964; Artikkelnr Noca: N.A.; Pad Count: 7
U8 = ADP2504: Buck-Boost Switching Regulator IC Positive Adjustable 2.8V 1 Output 1A; Manufacturer: Analog Devices; Manufacturer Part Number: ADP2504ACPZ-R7; Part number IPS: 00000004965; Artikkelnr Noca: N.A.; Pad Count: 10
U9 = ADP1708: LDO, Adjustable, 1 Output 1A, 8-LFCSP-WD (3x3); Manufacturer: Analog Devices; Manufacturer Part Number: ADP1708ACPZ-R7; Part number IPS: 00000004966; Artikkelnr Noca: N.A.; Pad Count: 9

## Sheet pca63100_misc.SchDoc: Power Profiler Kit II
size A3; Organization: Nordic Semiconductor; Revision: 1.0.1; SheetNumber: 6; SheetTotal: 6; Author: HANY; CompanyName: Nordic Semiconductor; DrawnBy: HANY; DocumentSize: A3
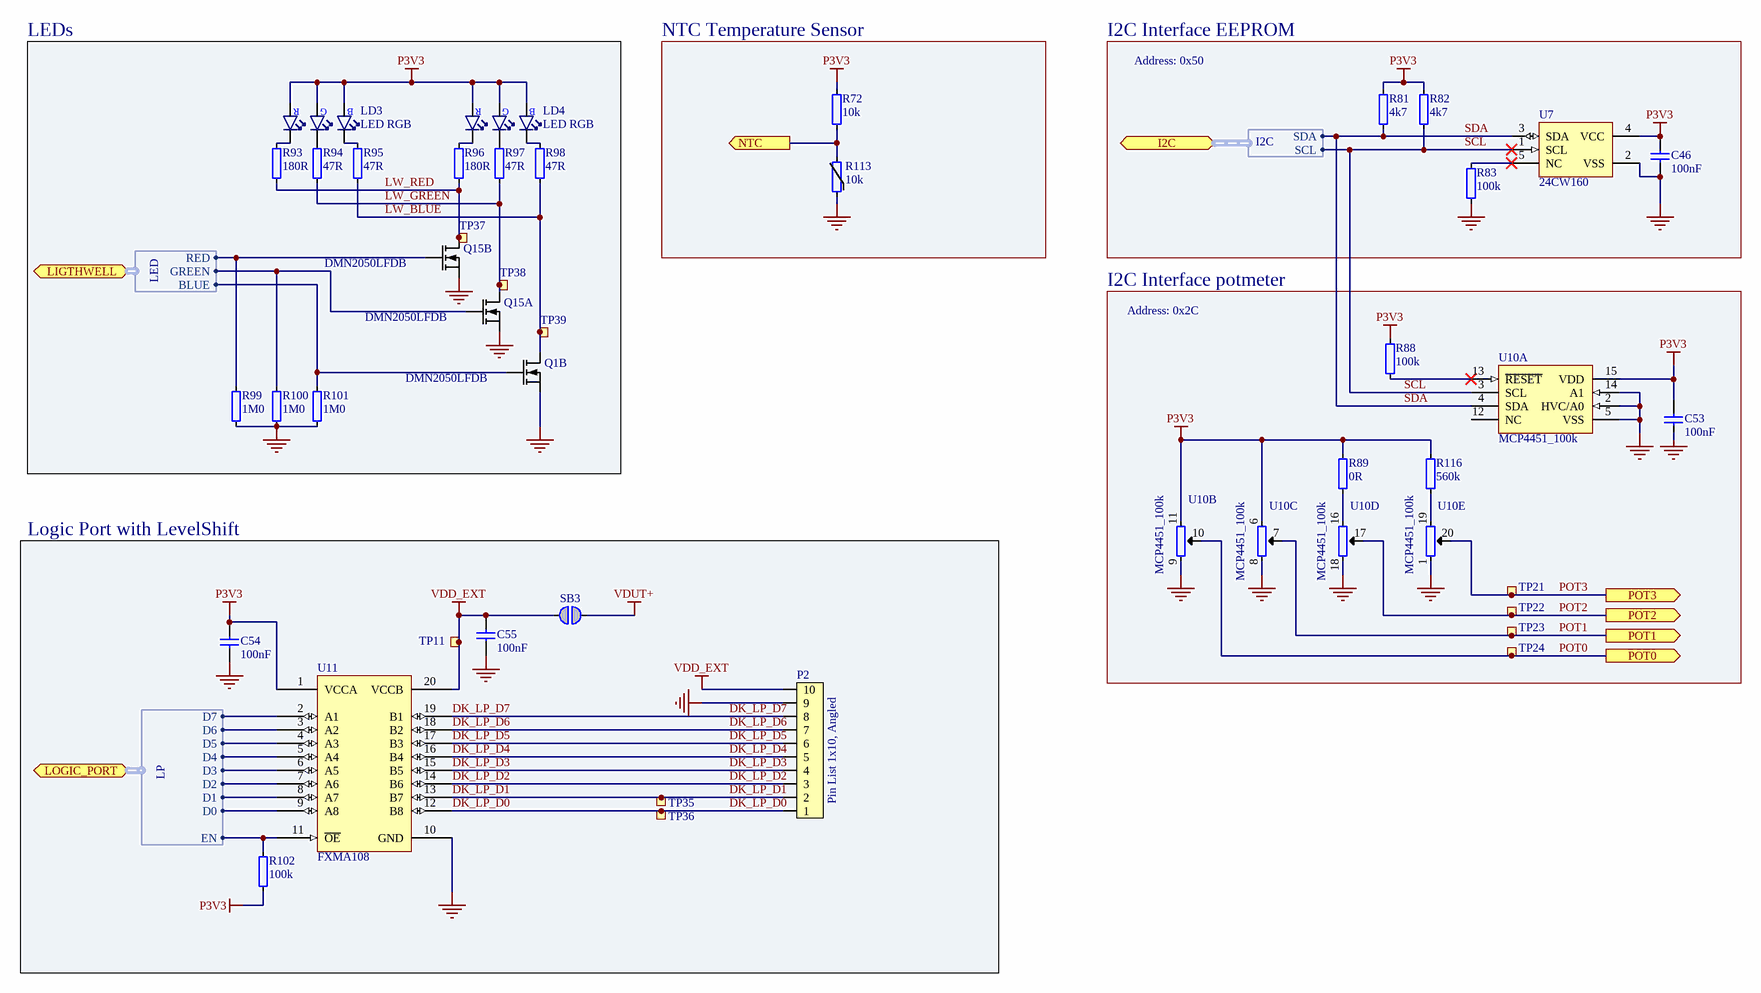
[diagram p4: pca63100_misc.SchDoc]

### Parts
C46  100nF  [CAPC0603X03L_C]
C53  100nF  [CAPC0603X03L_C]
C54  100nF  [CAPC0603X03L_C]
C55  100nF  [CAPC0603X03L_C]
LD3  LED RGB  [MSL0104]
LD4  LED RGB  [MSL0104]
P2  Pin List 1x10, Angled  [LIST_ANG_1x10-SMD-2.54MM]
Q1  DMN2050LFDB  [DFN65P200X60_HS-6N]  (part B of 2)
Q15  DMN2050LFDB  [DFN65P200X60_HS-6N]  (parts A,B of 2)
R72  10k  [RESC0603X03L_C]
R81  4k7  [RESC0603X03L_C]
R82  4k7  [RESC0603X03L_C]
R83  100k  [RESC0603X03L_C]
R88  100k  [RESC0603X03L_C]
R89  0R  [RESC0603X03L_C]
R93  180R  [RESC0603X03L_C]
R94  47R  [RESC0603X03L_C]
R95  47R  [RESC0603X03L_C]
R96  180R  [RESC0603X03L_C]
R97  47R  [RESC0603X03L_C]
R98  47R  [RESC0603X03L_C]
R99  1M0  [RESC0603X03L_C]
R100  1M0  [RESC0603X03L_C]
R101  1M0  [RESC0603X03L_C]
R102  100k  [RESC0603X03L_C]
R113  10k  [RESC1005X04L]
R116  560k  [RESC0603X03L_C]
SB3  Solderbridge  [Solderbridge]  (value not drawn)  (no BOM)
TP11  Ø1.5mm,SMD  [TP_SMD_Ø1.5mm]  (value not drawn)  (no BOM)
TP21  Ø0.7mm,SMD  [TP_SMD_Ø0.7mm]  (value not drawn)  (no BOM)
TP22  Ø0.7mm,SMD  [TP_SMD_Ø0.7mm]  (value not drawn)  (no BOM)
TP23  Ø0.7mm,SMD  [TP_SMD_Ø0.7mm]  (value not drawn)  (no BOM)
TP24  Ø0.7mm,SMD  [TP_SMD_Ø0.7mm]  (value not drawn)  (no BOM)
TP35  Ø1.5mm,SMD  [TP_SMD_Ø1.5mm]  (value not drawn)  (no BOM)
TP36  Ø1.5mm,SMD  [TP_SMD_Ø1.5mm]  (value not drawn)  (no BOM)
TP37  Ø0.7mm,SMD  [TP_SMD_Ø0.7mm]  (value not drawn)  (no BOM)
TP38  Ø0.7mm,SMD  [TP_SMD_Ø0.7mm]  (value not drawn)  (no BOM)
TP39  Ø0.7mm,SMD  [TP_SMD_Ø0.7mm]  (value not drawn)  (no BOM)
U7  24CW160  [SOT-23-5]
U10  MCP4451_100k  [QFN50P400X400X80_HS-21N]  (parts A,B,C,D,E of 5)
U11  FXMA108  [QFN50P450X250X80_HS-21N]

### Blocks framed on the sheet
LEDs: LD3 LD4 Q1 Q15 R93-R101 TP37-TP39
NTC Temperature Sensor: R72 R113
I2C Interface EEPROM: C46 R81-R83 U7
I2C Interface potmeter: C53 R88 R89 R116 TP21-TP24 U10
Logic Port with LevelShift: C54 C55 P2 R102 SB3 TP11 TP35 TP36 U11

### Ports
I2C (bidir, harness I2C), LIGTHWELL (bidir, harness LED), LOGIC_PORT (bidir, harness LP), NTC (out), POT0 (out), POT1 (out), POT2 (out), POT3 (out)

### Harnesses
LED: BLUE, GREEN, RED
LP: D0, EN, D1, D2, D3, D4, D5, D6, D7
I2C: SCL, SDA

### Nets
GND: C46.2 C53.1 C54.2 C55.2 P2.9 Q1.4(S2) Q15.1(S1) Q15.4(S2) R83.1 R99.1 R100.1 R101.1 R113.1 U7.2(VSS) U10.1(P3B) U10.2(HVC/A0) U10.5(VSS) U10.8(P1A) U10.9(P0A) U10.14(A1) U10.18(P2A) U10.21(VSS) U11.10(GND)
P3V3: C46.1 C53.2 C54.1 LD3.1(A_RED) LD3.2(A_GREEN) LD3.6(A_BLUE) LD4.1(A_RED) LD4.2(A_GREEN) LD4.6(A_BLUE) R72.2 R81.2 R82.2 R88.2 R89.2 R102.2 R116.2 U7.4(VCC) U10.6(P1B) U10.11(P0B) U10.15(VDD) U11.1(VCCA)
VDD_EXT: C55.1 P2.10 SB3.2 TP11.1 U11.20(VCCB)
VDUT+: SB3.1
DK_LP_D0: P2.1 TP36.1 U11.12(B8)
DK_LP_D1: P2.2 TP35.1 U11.13(B7)
DK_LP_D2: P2.3 U11.14(B6)
DK_LP_D3: P2.4 U11.15(B5)
DK_LP_D4: P2.5 U11.16(B4)
DK_LP_D5: P2.6 U11.17(B3)
DK_LP_D6: P2.7 U11.18(B2)
DK_LP_D7: P2.8 U11.19(B1)
LW_BLUE: Q1.3(D2) R95.1 R98.1 TP39.1
LW_GREEN: Q15.6(D1) R94.1 R97.1 TP38.1
LW_RED: Q15.3(D2) R93.1 R96.1 TP37.1
P0.09_LP_EN: R102.1 U11.11(~{OE}) ; port LOGIC_PORT.EN
P0.10_LP_D0: U11.9(A8) ; port LOGIC_PORT.D0
P0.11_LP_D1: U11.8(A7) ; port LOGIC_PORT.D1
P0.12_LP_D2: U11.7(A6) ; port LOGIC_PORT.D2
P0.13_LP_D3: U11.6(A5) ; port LOGIC_PORT.D3
P0.14_LP_D4: U11.5(A4) ; port LOGIC_PORT.D4
P0.15_LP_D5: U11.4(A3) ; port LOGIC_PORT.D5
P0.16_LP_D6: U11.3(A2) ; port LOGIC_PORT.D6
P0.17_LP_D7: U11.2(A1) ; port LOGIC_PORT.D7
P0.30/AIN6_NTC: R72.1 R113.2 ; port NTC
P1.05_LEDR: Q15.5(G2) R99.2 ; port LIGTHWELL.RED
P1.06_LEDG: Q15.2(G1) R100.2 ; port LIGTHWELL.GREEN
P1.07_LEDB: Q1.5(G2) R101.2 ; port LIGTHWELL.BLUE
POT0: TP24.1 U10.10(P0W) ; port POT0
POT1: TP23.1 U10.7(P1W) ; port POT1
POT2: TP22.1 U10.17(P2W) ; port POT2
POT3: TP21.1 U10.20(P3W) ; port POT3
SCL: R82.1 U7.1(SCL) U10.3(SCL) ; port I2C.SCL
SDA: R81.1 U7.3(SDA) U10.4(SDA) ; port I2C.SDA
NetLD3_3: LD3.3(C_GREEN) R94.2
NetLD3_4: LD3.4(C_RED) R93.2
NetLD3_5: LD3.5(C_BLUE) R95.2
NetLD4_3: LD4.3(C_GREEN) R97.2
NetLD4_4: LD4.4(C_RED) R96.2
NetLD4_5: LD4.5(C_BLUE) R98.2
NetR83_2: R83.2 U7.5(NC)
NetR88_1: R88.1 U10.13(~{RESET})
NetR89_1: R89.1 U10.16(P2B)
NetR116_1: R116.1 U10.19(P3A)

Not connected (* = marked no-connect by the designer): U10 12(NC)

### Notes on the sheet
- Address: 0x50
- Address: 0x2C

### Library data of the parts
C46 C53-C55 = C0201-100n: as C2 on sheet pca63100_current_automatic_switch
LD3 LD4 = MSL0104RGBU1: High brightness, side view RGB LED; Manufacturer: ROHM; Part number IPS: 00000007799; Artikkelnr Noca: N.A.; Pad Count: 7
P2 = Pin List Ang 1x10 SMD, 2.54mm: Pin List 1x10, 2.54mm (100mil), Right Angled, SMD; Part number IPS: 00000004781; Artikkelnr Noca: N.A.; Pad Count: 10
Q1 Q15 = DMN2050LFDB: as Q1 on sheet pca63100_current_measurement
R72 = R0201-10k_0.1%: as R3 on sheet pca63100_current_automatic_switch
R81 R82 = R0201-4k7: as R19 on sheet pca63100_current_automatic_switch
R83 R88 R102 = R0201-100k: as R37 on sheet pca63100_current_measurement
R89 = R0201-0R: as R114 on sheet pca63100_power_supply
R93 R96 = R0201-180: Resistor, ±1%, 0.05W; Part number IPS: 00000005783; Note: Chip Res 1%; Artikkelnr Noca: N.A.; Pad Count: 2
R94 R95 R97 R98 = R0201-47R: as R44 on sheet pca63100_current_measurement
R99-R101 = R0201-1M0: as R35 on sheet pca63100_current_measurement
R113 = NCP15XH103F03RC: THERMISTOR 10K OHM NTC 0402 SMD; Manufacturer: Murata; Part number IPS: 00000007808; Note: Chip Res 1%; Artikkelnr Noca: N.A.; Pad Count: 2
R116 = R0201-560k: as R79 on sheet pca63100_power_supply
SB3 = Solderbridge: Artikkelnr Noca: N.A.; Pad Count: 2
TP11 TP35 TP36 = TP_SMD_Ø1.5MM: as TP6 on sheet pca63100_current_measurement
TP21-TP24 TP37-TP39 = TP_SMD_Ø0.7MM: as TP1 on sheet pca63100_current_automatic_switch
U7 = 24CW160T-I/OT: 16 Kbit I2C Serial EEPROM with Software Write Protection, 1.6-5.5 V Supply; Manufacturer: Microchip; Part number IPS: 00000004049; Artikkelnr Noca: N.A.; Pad Count: 5
U10 = MCP4451_100k: Quad Digital Potentiometer, 100k, 257 taps, I2C interface, Volatile Memory, 1.8-5.5V; Manufacturer: Microchip Technology; Manufacturer Part Number: MCP4451-104E/ML; Part number IPS: 00000004805; Artikkelnr Noca: 15070064; Pad Count: 20
U11 = FXMA108BQX: 8-bit bidirectional voltage-level translator with auto-direction sensing; Manufacturer: Fairchild Semiconductor; Part number IPS: 00000004806; Note: Translator, Bidirectional; Artikkelnr Noca: N.A.; Pad Count: 20

## Sheet pca63100_mcu.SchDoc: Power Profiler Kit II
size A3; Organization: Nordic Semiconductor; DocumentNumber: 0; Revision: 1.0.1; SheetNumber: 2; SheetTotal: 6; Author: HANY; CompanyName: Nordic Semiconductor; DrawnBy: HANY; DocumentSize: A3
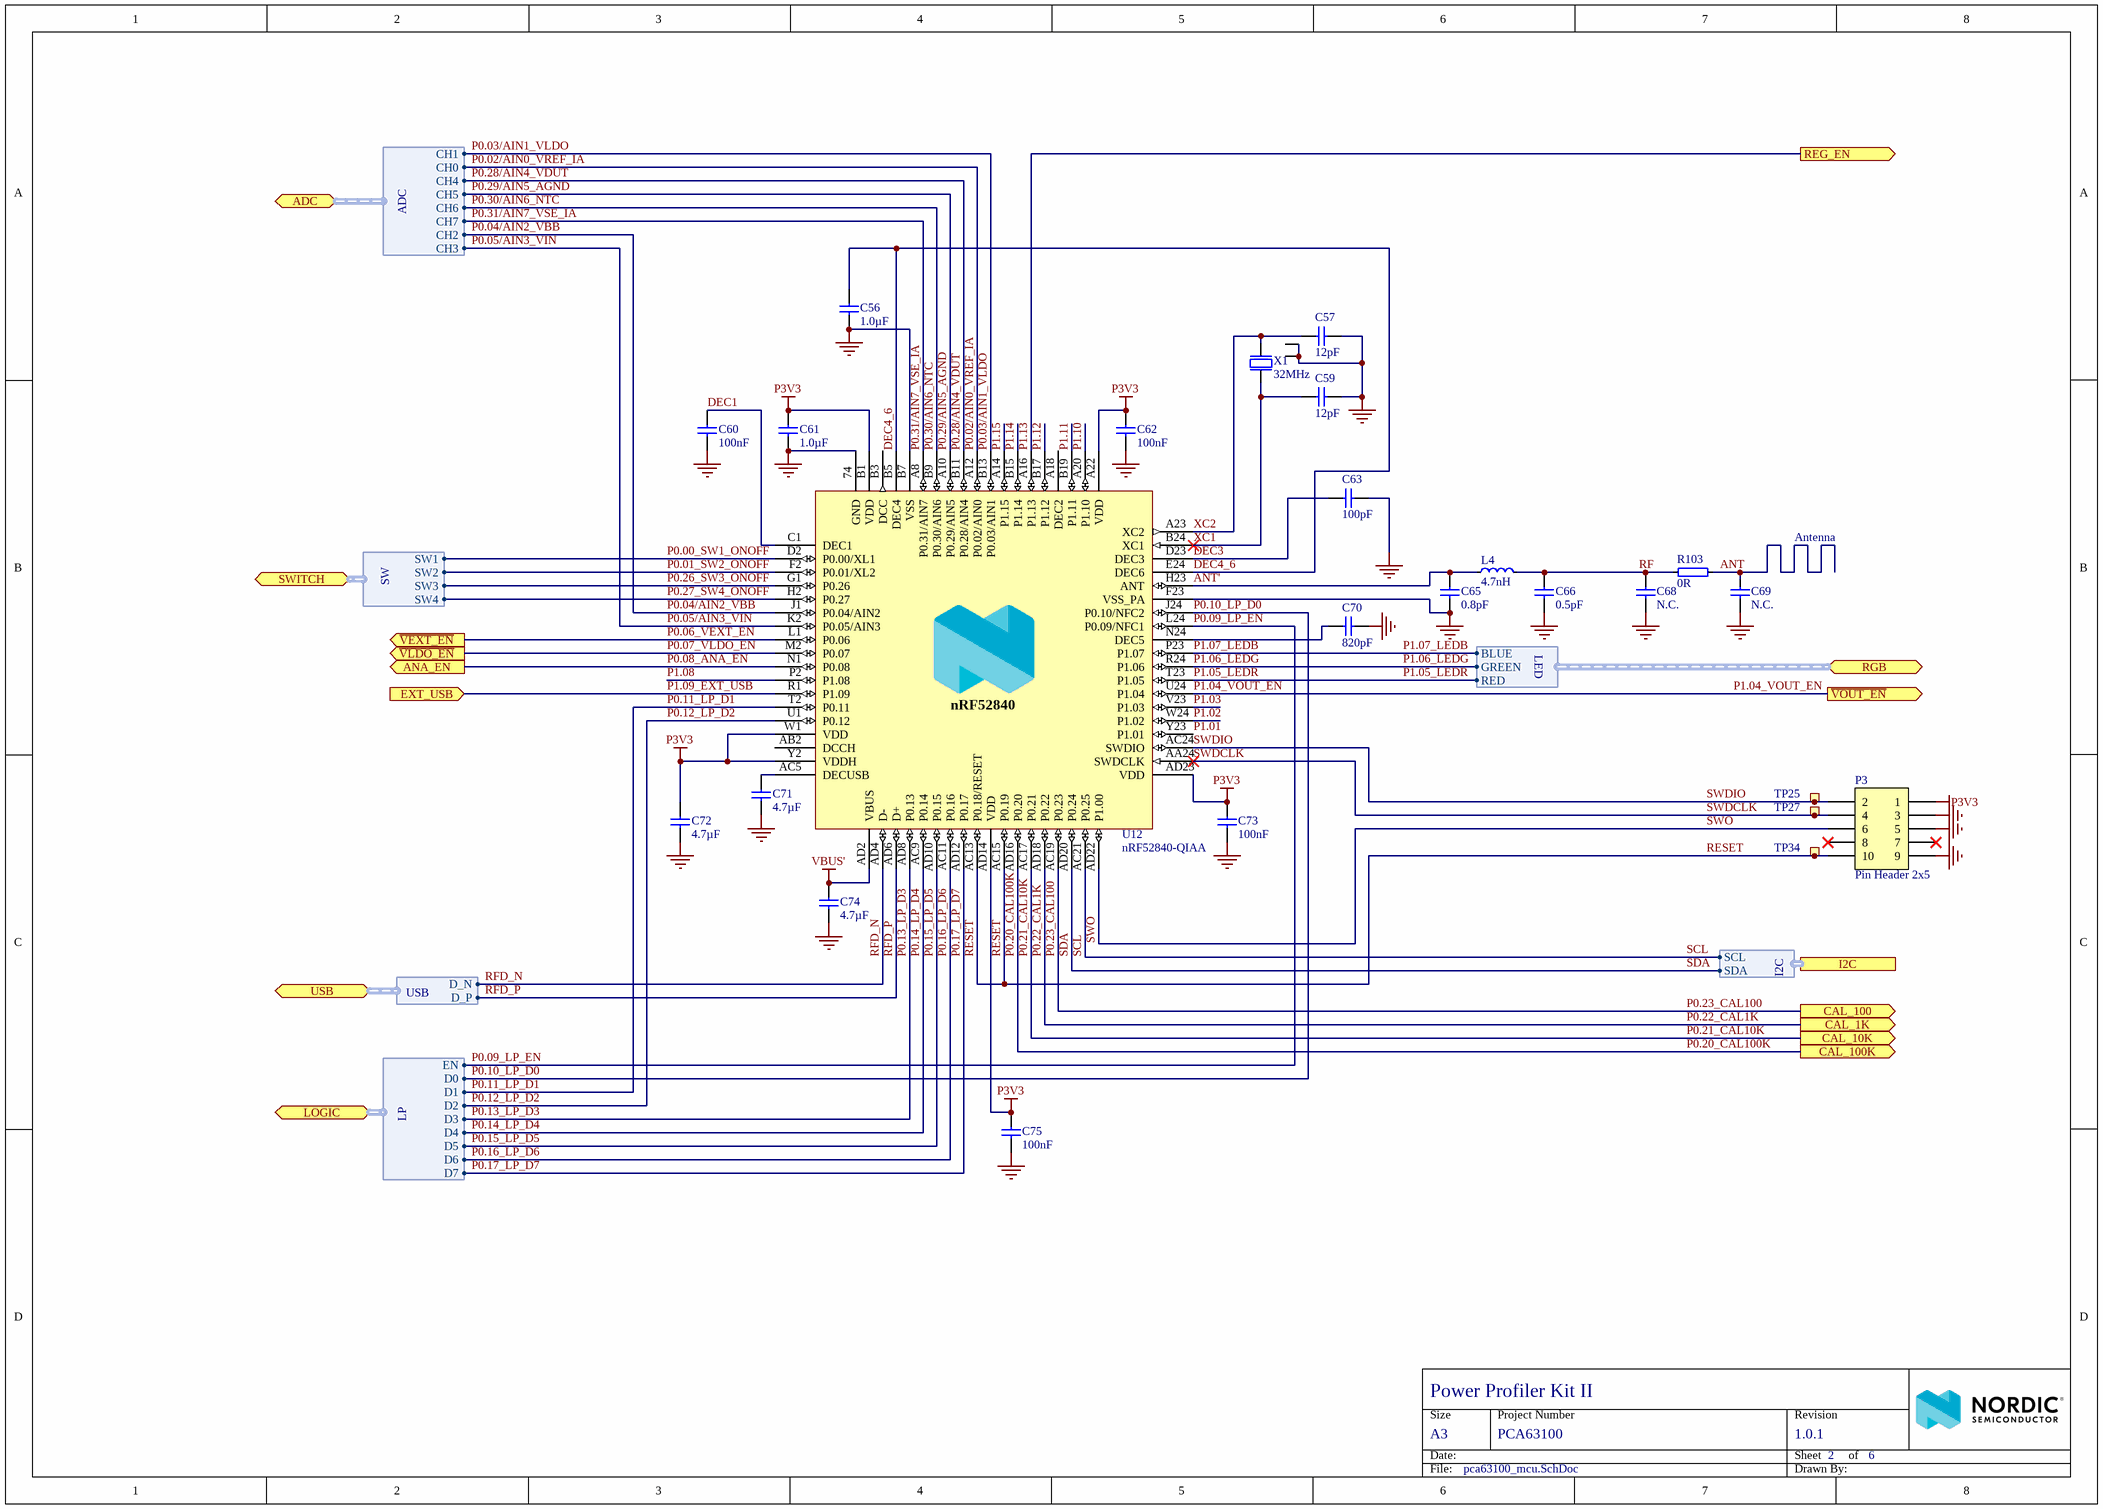
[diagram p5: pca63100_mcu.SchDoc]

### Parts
C56  1.0µF  [CAPC1005X04L]
C57  12pF  [CAPC1005X04L]
C59  12pF  [CAPC1005X04L]
C60  100nF  [CAPC0603X03L_C]
C61  1.0µF  [CAPC1005X04L]
C62  100nF  [CAPC0603X03L_C]
C63  100pF  [CAPC0603X03L_C]
C65  0.8pF  [CAPC1005X04L]
C66  0.5pF  [CAPC1005X04L]
C68  N.C.  [CAPC1005X04L_NC]
C69  N.C.  [CAPC1005X04L_NC]
C70  820pF  [CAPC1005X04L]
C71  4.7µF  [CAPC1005X04L]
C72  4.7µF  [CAPC1005X04L]
C73  100nF  [CAPC0603X03L_C]
C74  4.7µF  [CAPC1005X04L]
C75  100nF  [CAPC0603X03L_C]
L4  4.7nH  [INDC1005X04L]
P3  Pin Header 2x5  [HDR_2x5-SMD-1.27mm-ANG]
R103  0R  [RESC1005X04L]
TP25  Ø1.5mm,SMD  [TP_SMD_Ø1.5mm]  (value not drawn)  (no BOM)
TP27  Ø1.5mm,SMD  [TP_SMD_Ø1.5mm]  (value not drawn)  (no BOM)
TP34  Ø1.5mm,SMD  [TP_SMD_Ø1.5mm]  (value not drawn)  (no BOM)
U12  nRF52840-QIAA  [AQFN50P700X700X85_HS-74N]
X1  32MHz  [BT-XTAL_2016]

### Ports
ADC (bidir, harness ADC), ANA_EN (out), CAL_1K (out), CAL_10K (out), CAL_100 (out), CAL_100K (out), EXT_USB (in), I2C (harness I2C), LOGIC (bidir, harness LP), REG_EN (out), RGB (bidir, harness LED), SWITCH (bidir, harness SW), USB (bidir, harness USB), ~{VEXT_EN} (out), ~{VLDO_EN} (out), ~{VOUT_EN} (out)

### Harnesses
LP: D0, EN, D1, D2, D3, D4, D5, D6, D7
USB: D_N, D_P
LED: BLUE, GREEN, RED
SW: SW1, SW2, SW3, SW4
I2C: SCL, SDA
ADC: CH0, CH1, CH2, CH3, CH4, CH5, CH6, CH7

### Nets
GND: C56.1 C57.2 C59.2 C60.2 C61.2 C62.2 C63.2 C65.1 C66.1 C68.1 C69.1 C70.2 C71.2 C72.2 C73.2 C74.2 C75.2 P3.3 P3.5 P3.9 U12.74(GND) U12.B7(VSS) U12.F23(VSS_PA) X1.2(GND) X1.4(GND)
P3V3: C61.1 C62.1 C72.1 C73.1 C75.1 P3.1 U12.A22(VDD) U12.AD14(VDD) U12.AD23(VDD) U12.B1(VDD) U12.W1(VDD) U12.Y2(VDDH)
VBUS': C74.1 U12.AD2(VBUS)
ANT: C69.2 R103.2
ANT': C65.2 L4.1 U12.H23(ANT)
DEC1: C60.1 U12.C1(DEC1)
DEC3: C63.1 U12.D23(DEC3)
DEC4_6: C56.2 U12.B5(DEC4) U12.E24(DEC6)
P0.00_SW1_ONOFF: U12.D2(P0.00/XL1) ; port SWITCH.SW1
P0.01_SW2_ONOFF: U12.F2(P0.01/XL2) ; port SWITCH.SW2
P0.02/AIN0_VREF_IA: U12.A12(P0.02/AIN0) ; port ADC.CH0
P0.03/AIN1_VLDO: U12.B13(P0.03/AIN1) ; port ADC.CH1
P0.04/AIN2_VBB: U12.J1(P0.04/AIN2) ; port ADC.CH2
P0.05/AIN3_VIN: U12.K2(P0.05/AIN3) ; port ADC.CH3
P0.06_VEXT_EN: U12.L1(P0.06) ; port ~{VEXT_EN}
P0.07_VLDO_EN: U12.M2(P0.07) ; port ~{VLDO_EN}
P0.08_ANA_EN: U12.N1(P0.08) ; port ANA_EN
P0.09_LP_EN: U12.L24(P0.09/NFC1) ; port LOGIC.EN
P0.10_LP_D0: U12.J24(P0.10/NFC2) ; port LOGIC.D0
P0.11_LP_D1: U12.T2(P0.11) ; port LOGIC.D1
P0.12_LP_D2: U12.U1(P0.12) ; port LOGIC.D2
P0.13_LP_D3: U12.AD8(P0.13) ; port LOGIC.D3
P0.14_LP_D4: U12.AC9(P0.14) ; port LOGIC.D4
P0.15_LP_D5: U12.AD10(P0.15) ; port LOGIC.D5
P0.16_LP_D6: U12.AC11(P0.16) ; port LOGIC.D6
P0.17_LP_D7: U12.AD12(P0.17) ; port LOGIC.D7
P0.20_CAL100K: U12.AD16(P0.20) ; port CAL_100K
P0.21_CAL10K: U12.AC17(P0.21) ; port CAL_10K
P0.22_CAL1K: U12.AD18(P0.22) ; port CAL_1K
P0.23_CAL100: U12.AC19(P0.23) ; port CAL_100
P0.26_SW3_ONOFF: U12.G1(P0.26) ; port SWITCH.SW3
P0.27_SW4_ONOFF: U12.H2(P0.27) ; port SWITCH.SW4
P0.28/AIN4_VDUT: U12.B11(P0.28/AIN4) ; port ADC.CH4
P0.29/AIN5_AGND: U12.A10(P0.29/AIN5) ; port ADC.CH5
P0.30/AIN6_NTC: U12.B9(P0.30/AIN6) ; port ADC.CH6
P0.31/AIN7_VSE_IA: U12.A8(P0.31/AIN7) ; port ADC.CH7
P1.01: U12.Y23(P1.01)
P1.02: U12.W24(P1.02)
P1.03: U12.V23(P1.03)
P1.04_VOUT_EN: U12.U24(P1.04) ; port ~{VOUT_EN}
P1.05_LEDR: U12.T23(P1.05) ; port RGB.RED
P1.06_LEDG: U12.R24(P1.06) ; port RGB.GREEN
P1.07_LEDB: U12.P23(P1.07) ; port RGB.BLUE
P1.08: U12.P2(P1.08)
P1.09_EXT_USB: U12.R1(P1.09) ; port EXT_USB
P1.10: U12.A20(P1.10)
P1.11: U12.B19(P1.11)
P1.12: U12.B17(P1.12)
P1.13: U12.A16(P1.13) ; port REG_EN
P1.14: U12.B15(P1.14)
P1.15: U12.A14(P1.15)
RESET: P3.10 TP34.1 U12.AC13(P0.18/RESET) U12.AC15(P0.19)
RF: C66.2 C68.2 L4.2 R103.1
RFD_N: U12.AD4(D-) ; port USB.D_N
RFD_P: U12.AD6(D+) ; port USB.D_P
SCL: U12.AC21(P0.25) ; port I2C.SCL
SDA: U12.AD20(P0.24) ; port I2C.SDA
SWDCLK: P3.4 TP27.1 U12.AA24(SWDCLK)
SWDIO: P3.2 TP25.1 U12.AC24(SWDIO)
SWO: P3.6 U12.AD22(P1.00)
XC1: C59.1 U12.B24(XC1) X1.1(inp)
XC2: C57.1 U12.A23(XC2) X1.3(out)
NetC70_1: C70.1 U12.N24(DEC5)
NetC71_1: C71.1 U12.AC5(DECUSB)

Not connected (* = marked no-connect by the designer): P3 7* 8*; U12 A18(DEC2) AB2(DCCH) B3(DCC)

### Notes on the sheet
- Antenna

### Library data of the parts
C56 C61 = C0402-1µ0: as C40 on sheet pca63100_power_supply
C57 C59 = C0402-12p: Capacitor, NP0, ±2%; Part number IPS: 00000002398; Note: 50V; Artikkelnr Noca: 20029159; Pad Count: 2
C60 C62 C73 C75 = C0201-100n: as C2 on sheet pca63100_current_automatic_switch
C63 = C0201-100p: Capacitor, NP0, ±2%, 25V; Manufacturer: Murata; Manufacturer Part Number: GRM0335C1E101GA01; Part number IPS: 00000007853; Artikkelnr Noca: N.A.; Pad Count: 2
C65 = C0402-0.8p: Capacitor, NP0, ±5%; Manufacturer: Murata; Manufacturer Part Number: GRM1555C1HR80WA01D; Part number IPS: 00000007782; Note: 50V; Artikkelnr Noca: 20029147; Pad Count: 2
C66 = C0402-0.5p: Capacitor, NP0, ±0.05pF; Manufacturer: Murata; Manufacturer Part Number: GJM1555C1HR50WB01; Part number IPS: 00000004293; Note: 50V; Artikkelnr Noca: 20020007; Pad Count: 2
C68 C69 = C0402-N.C.: Not mounted; Note: Chip Cap; Artikkelnr Noca: N.A.; Assembly: Not mounted; Pad Count: 2
C70 = C0402-820p: Capacitor, NP0, ±5%; Part number IPS: 00000004365; Note: 50V; Artikkelnr Noca: 20029219; Pad Count: 2
C71 C72 C74 = C0402-4µ7: as C18 on sheet pca63100_current_measurement
L4 = L0402-4n7: Inductor, 160mA, ±0.1nH; Manufacturer: Murata; Manufacturer Part Number: LQP15MN4N7B02D; Part number IPS: 00000004366; Note: High frequency chip inductor ±5%; Artikkelnr Noca: 33029164; Pad Count: 2
P3 = Pin Header 2x5 SMD, 1.27mm, Angled: Pin Header 2x5, 1.27mm (50mil); Manufacturer: W-CON; Manufacturer Part Number: 1325B-1205S0Z080CR02; Part number IPS: 00000007800; Artikkelnr Noca: N.A.; Pad Count: 10
R103 = R0402-0R: Resistor, ±5%, 0.063W; Part number IPS: 00000007128; Note: Chip Res 5%; Artikkelnr Noca: 27049000; Pad Count: 2
TP25 TP27 TP34 = TP_SMD_Ø1.5MM: as TP6 on sheet pca63100_current_measurement
U12 = nRF52840-QIAAD0: Multi-protocol Bluetooth Low Energy, IEEE 802.15.4, ANT and 2.4GHz proprietary system-on-chip; Manufacturer: Nordic Semiconductor; Part number IPS: 80000001648; Artikkelnr Noca: N.A.; Pad Count: 73
X1 = XTAL_SMD2016_32MHz_8pF_General: XTAL SMD 2016, 32MHz, Cl=8pF, Total Tol: ±40ppm; Part number IPS: 00000007827; Note: XTAL SMD 32.000MHz; Artikkelnr Noca: N.A.; Pad Count: 4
